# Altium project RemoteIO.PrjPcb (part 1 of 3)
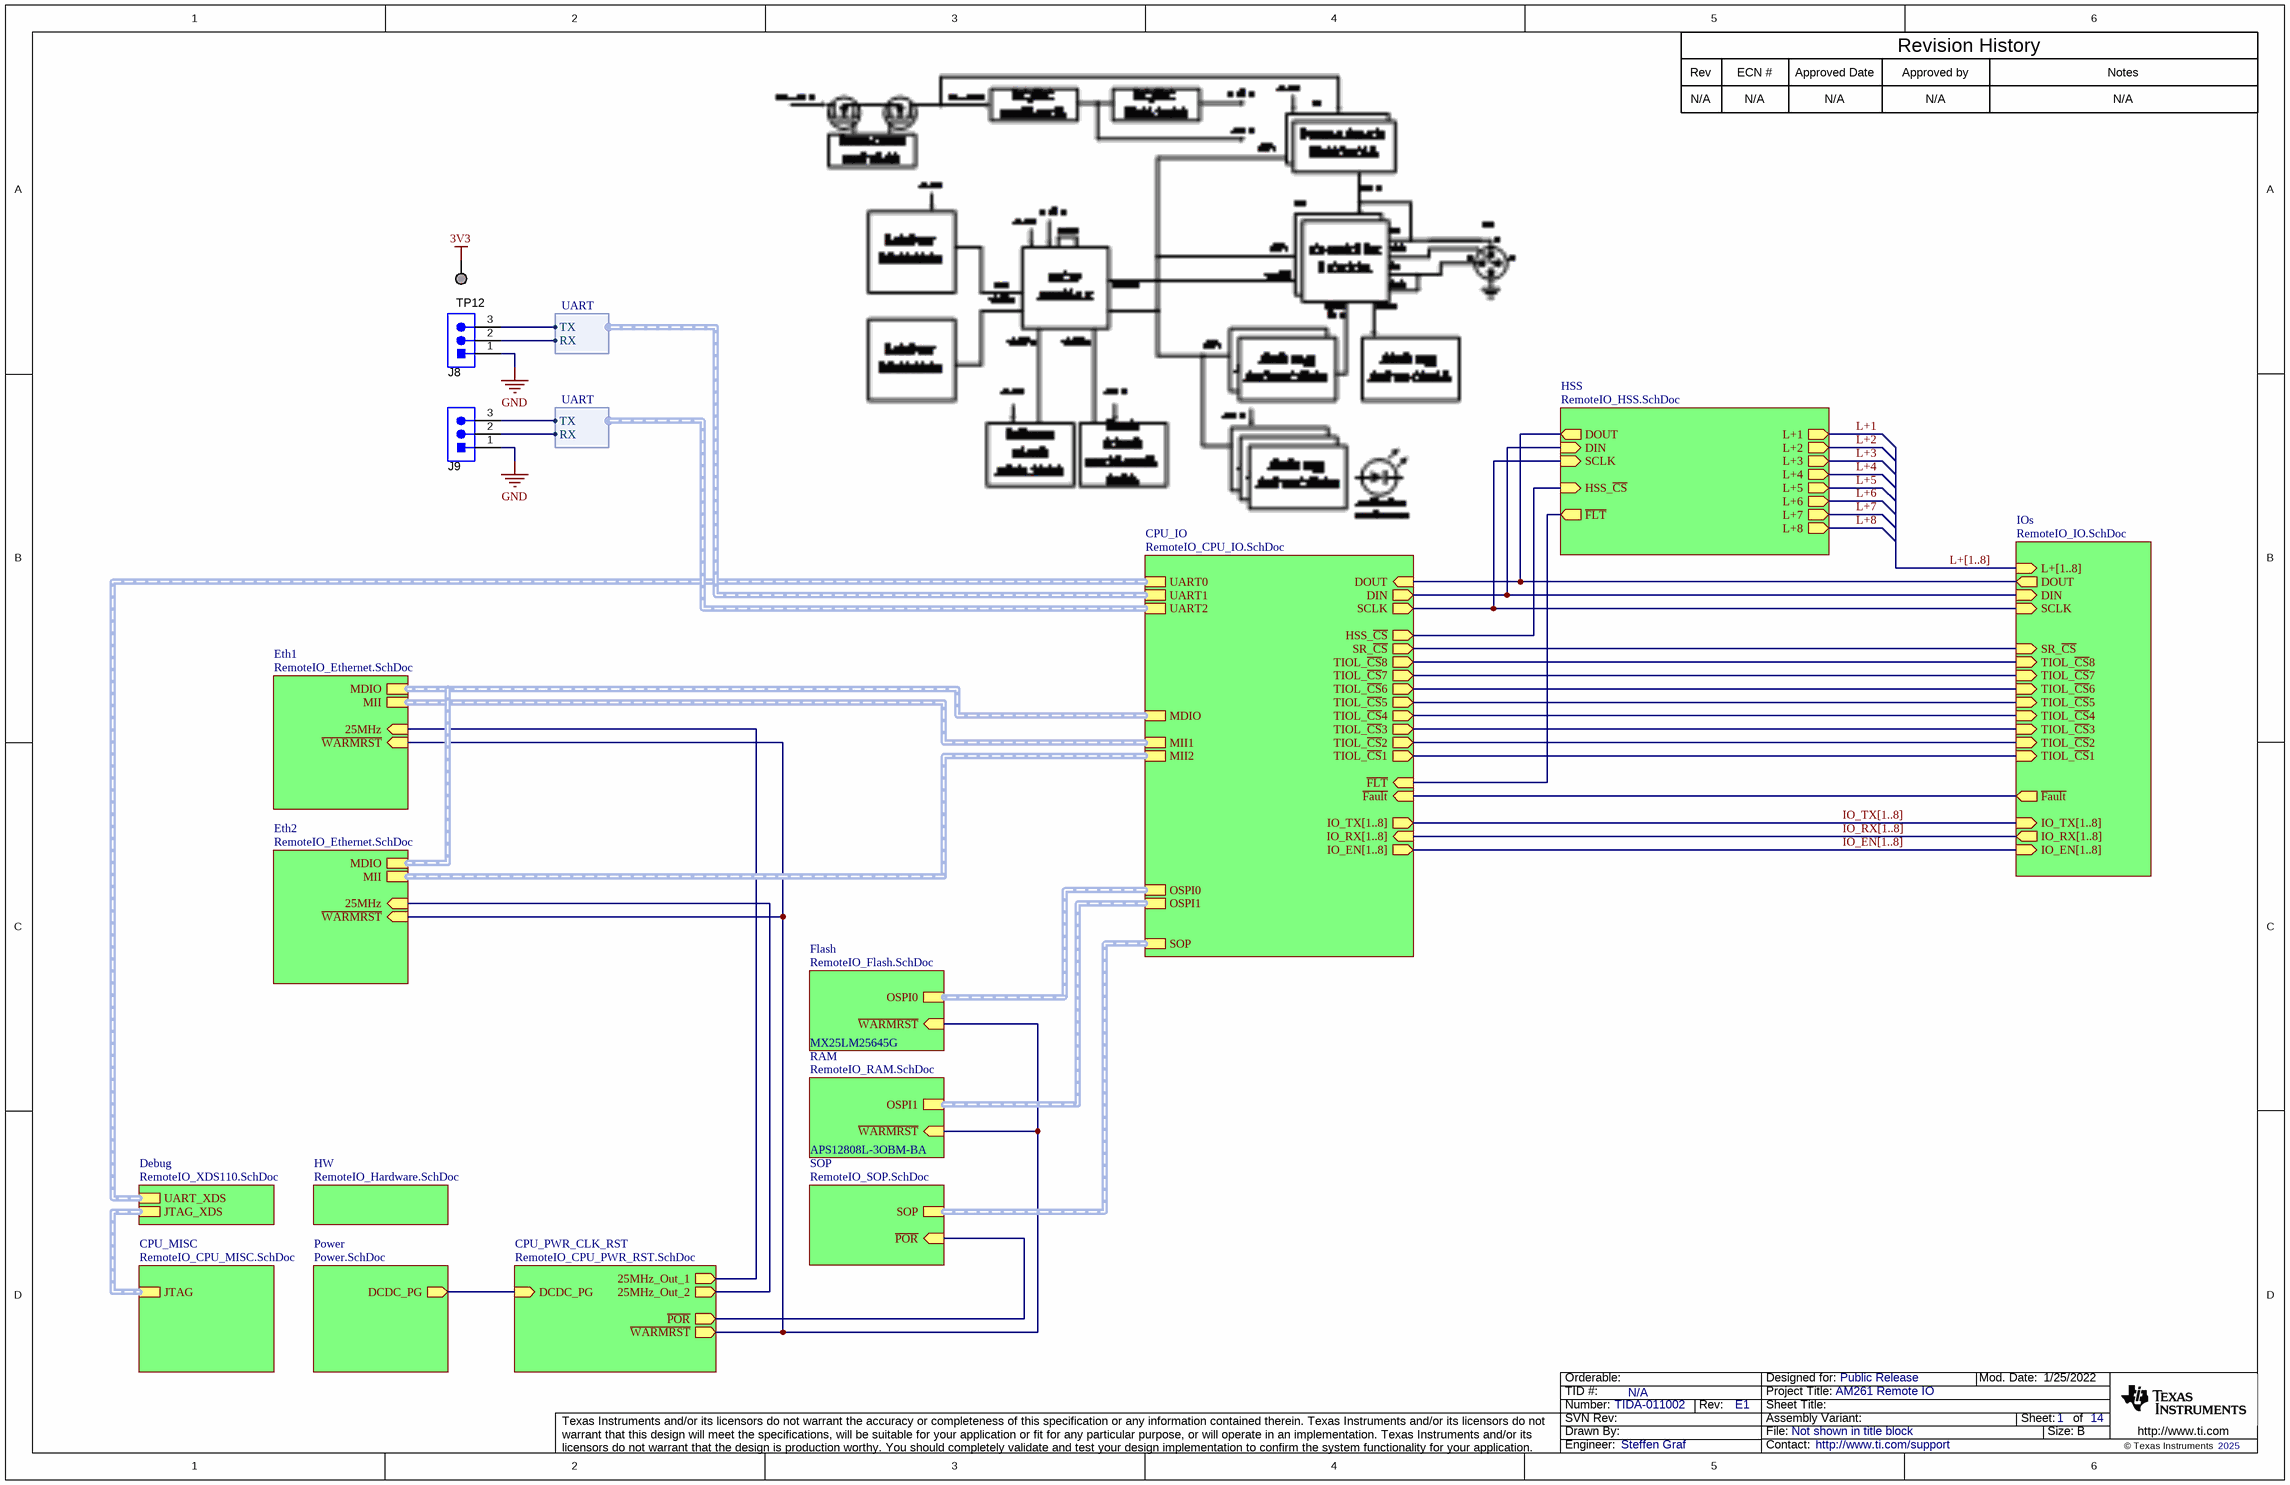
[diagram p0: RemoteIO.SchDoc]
CopyrightYear: 2025; PCB_Layout: Steffen Graf; PCB_Rev: E1; PRJ_Customer: Public Release; PRJ_Engineer: Steffen Graf; PRJ_Number: TIDA-011002; PRJ_Title: AM261 Remote IO; SCH_Rev: E1; TechSupport: http://www.ti.com/support; TID: N/A
13 sheets, 600 parts. Net scope: hierarchical (ports join the sheet entries above them; power ports are global).
Board file: RemoteIO.PcbDoc
Sheets:
  RemoteIO.SchDoc
    Eth1 = RemoteIO_Ethernet.SchDoc
    Eth2 = RemoteIO_Ethernet.SchDoc
    CPU_IO = RemoteIO_CPU_IO.SchDoc
    IOs = RemoteIO_IO.SchDoc
      IO1 = RemoteIO_IOLinkPort.SchDoc
      IO2 = RemoteIO_IOLinkPort.SchDoc
      IO3 = RemoteIO_IOLinkPort.SchDoc
      IO4 = RemoteIO_IOLinkPort.SchDoc
      IO5 = RemoteIO_IOLinkPort.SchDoc
      IO6 = RemoteIO_IOLinkPort.SchDoc
      IO7 = RemoteIO_IOLinkPort.SchDoc
      IO8 = RemoteIO_IOLinkPort.SchDoc
    HW = RemoteIO_Hardware.SchDoc
    HSS = RemoteIO_HSS.SchDoc
    Flash = RemoteIO_Flash.SchDoc
    RAM = RemoteIO_RAM.SchDoc
    SOP = RemoteIO_SOP.SchDoc
    CPU_PWR_CLK_RST = RemoteIO_CPU_PWR_RST.SchDoc
    CPU_MISC = RemoteIO_CPU_MISC.SchDoc
    Debug = RemoteIO_XDS110.SchDoc

## Sheet RemoteIO.SchDoc
size 431 x 279 mm; Date: Not shown in title block; ApprovedBy: Not shown in title block; CheckedBy: Not shown in title block; Author: Not shown in title block; CompanyName: Not shown in title block; Engineer: Not shown in title block; Organization: Not shown in title block; Address1: Not shown in title block; Address2: Not shown in title block; Address3: Not shown in title block; Address4: Not shown in title block; DocumentNumber: 1; Revision: Use project parameter SCH_Rev; SheetNumber: 1; SheetTotal: 14; PageSetup: Record=PageOptions¦CenterHorizontal=True¦CenterVertical=True¦PrintScale=1.00¦XCorrection=1.00¦YCorrection=1.00¦PrintKind=0¦BorderSize=5000000¦LeftOffset=0¦BottomOffset=0¦Orientation=2¦PaperLength=1000¦PaperWidth=1000¦Scale=100¦PaperSource=15¦PrintQuality=600¦MediaType=1¦DitherType=10¦PaperKind=Letter¦PrintScaleMode=1

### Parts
J8  61300311121  [WURTH_61300311121]  (value not drawn)
J9  61300311121  [WURTH_61300311121]  (value not drawn)
TP12  TESTPOINT  [TP_50MIL-25MILHOLE]  (value not drawn)  (no BOM)

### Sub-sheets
CPU_IO = RemoteIO_CPU_IO.SchDoc: DOUT (in), DIN (out), SCLK (out), HSS_~{CS} (out), SR_~{CS} (out), TIOL_~{CS}8 (out), TIOL_~{CS}7 (out), TIOL_~{CS}6 (out), TIOL_~{CS}5 (out), TIOL_~{CS}4 (out), TIOL_~{CS}3 (out), TIOL_~{CS}2 (out), TIOL_~{CS}1 (out), ~{FLT} (in), ~{Fault} (in), IO_TX[1..8] (out), IO_RX[1..8] (in), IO_EN[1..8] (out), MII1 (harness MII), MII2 (harness MII), MDIO (harness MDIO), UART0 (harness UART), UART1 (harness UART), OSPI0 (harness OSPI), OSPI1 (harness OSPI), SOP (harness SOP), UART2 (harness UART)
CPU_MISC = RemoteIO_CPU_MISC.SchDoc: JTAG (harness JTAG)
CPU_PWR_CLK_RST = RemoteIO_CPU_PWR_RST.SchDoc: DCDC_PG (in), ~{POR} (out), ~{WARMRST} (out), 25MHz_Out_1 (out), 25MHz_Out_2 (out)
Debug = RemoteIO_XDS110.SchDoc: JTAG_XDS (harness JTAG), UART_XDS (harness UART)
Eth1 = RemoteIO_Ethernet.SchDoc: MII, MDIO, 25MHz (in), ~{WARMRST} (in)
Eth2 = RemoteIO_Ethernet.SchDoc: MII, MDIO, 25MHz (in), ~{WARMRST} (in)
Flash = RemoteIO_Flash.SchDoc: OSPI0 (harness OSPI), ~{WARMRST} (in)
HSS = RemoteIO_HSS.SchDoc: L+1 (out), L+2 (out), L+3 (out), L+4 (out), L+5 (out), L+6 (out), L+7 (out), L+8 (out), HSS_~{CS} (in), SCLK (in), DIN (in), DOUT (out), ~{FLT} (out)
HW = RemoteIO_Hardware.SchDoc: no entries
IOs = RemoteIO_IO.SchDoc: SR_~{CS} (in), ~{Fault} (out), TIOL_~{CS}8 (in), TIOL_~{CS}7 (in), TIOL_~{CS}6 (in), TIOL_~{CS}5 (in), TIOL_~{CS}4 (in), TIOL_~{CS}3 (in), TIOL_~{CS}2 (in), TIOL_~{CS}1 (in), SCLK (in), DIN (in), DOUT (out), L+[1..8] (in), IO_RX[1..8] (out), IO_TX[1..8] (in), IO_EN[1..8] (in)
Power = Power.SchDoc (file not in this document): DCDC_PG (out)
RAM = RemoteIO_RAM.SchDoc: OSPI1, ~{WARMRST} (in)
SOP = RemoteIO_SOP.SchDoc: SOP (harness SOP), ~{POR} (in)

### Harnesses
UART: TX, RX

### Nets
3V3: TP12.1
GND: J8.1 J9.1
25MHz: sheet Eth1/25MHz, sheet CPU_PWR_CLK_RST/25MHz_Out_1
25MHz: sheet Eth2/25MHz, sheet CPU_PWR_CLK_RST/25MHz_Out_2  [a separate net that carries the same name]
~{Fault}: sheet CPU_IO/~{Fault}, sheet IOs/~{Fault}
~{FLT}: sheet CPU_IO/~{FLT}, sheet HSS/~{FLT}
~{POR}: sheet SOP/~{POR}, sheet CPU_PWR_CLK_RST/~{POR}
~{WARMRST}: sheet Eth1/~{WARMRST}, sheet Eth2/~{WARMRST}, sheet Flash/~{WARMRST}, sheet RAM/~{WARMRST}, sheet CPU_PWR_CLK_RST/~{WARMRST}
CS1: sheet CPU_IO/TIOL_~{CS}1, sheet IOs/TIOL_~{CS}1
CS2: sheet CPU_IO/TIOL_~{CS}2, sheet IOs/TIOL_~{CS}2
CS3: sheet CPU_IO/TIOL_~{CS}3, sheet IOs/TIOL_~{CS}3
CS4: sheet CPU_IO/TIOL_~{CS}4, sheet IOs/TIOL_~{CS}4
CS5: sheet CPU_IO/TIOL_~{CS}5, sheet IOs/TIOL_~{CS}5
CS6: sheet CPU_IO/TIOL_~{CS}6, sheet IOs/TIOL_~{CS}6
CS7: sheet CPU_IO/TIOL_~{CS}7, sheet IOs/TIOL_~{CS}7
CS8: sheet CPU_IO/TIOL_~{CS}8, sheet IOs/TIOL_~{CS}8
DCDC_PG: sheet Power/DCDC_PG, sheet CPU_PWR_CLK_RST/DCDC_PG
DIN: sheet CPU_IO/DIN, sheet IOs/DIN, sheet HSS/DIN
DOUT: sheet CPU_IO/DOUT, sheet IOs/DOUT, sheet HSS/DOUT
HSS_~{CS}: sheet CPU_IO/HSS_~{CS}, sheet HSS/HSS_~{CS}
SCLK: sheet CPU_IO/SCLK, sheet IOs/SCLK, sheet HSS/SCLK
SR_~{CS}: sheet CPU_IO/SR_~{CS}, sheet IOs/SR_~{CS}
UART1_RX: J8.2 ; sheet CPU_IO/UART1.RX
UART1_TX: J8.3 ; sheet CPU_IO/UART1.TX
NetJ9_2: J9.2 ; sheet CPU_IO/UART2.RX
NetJ9_3: J9.3 ; sheet CPU_IO/UART2.TX

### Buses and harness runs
bus IO_EN[1..8] = sheet CPU_IO/IO_EN[1..8] = sheet IOs/IO_EN[1..8]
bus IO_RX[1..8] = sheet CPU_IO/IO_RX[1..8] = sheet IOs/IO_RX[1..8]
bus IO_TX[1..8] = sheet CPU_IO/IO_TX[1..8] = sheet IOs/IO_TX[1..8]
bus L+[1..8] = sheet IOs/L+[1..8]
harness sheet CPU_IO/MDIO = sheet Eth1/MDIO = sheet Eth2/MDIO
harness sheet CPU_IO/MII1 = sheet Eth1/MII
harness sheet CPU_IO/MII2 = sheet Eth2/MII
harness sheet CPU_IO/OSPI0 = sheet Flash/OSPI0
harness sheet CPU_IO/OSPI1 = sheet RAM/OSPI1
harness sheet CPU_IO/SOP = sheet SOP/SOP
harness sheet CPU_IO/UART0 = sheet Debug/UART_XDS
harness sheet CPU_MISC/JTAG = sheet Debug/JTAG_XDS

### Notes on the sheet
- Rev
- N/A
- ECN #
- Approved Date
- Approved by
- Revision History
- Notes
- MX25LM25645G
- APS12808L-3OBM-BA

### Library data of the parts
J8 J9 = CMP-0054796-4: Header, 2.54 mm, 3x1, Gold, TH; Manufacturer: Wurth Elektronik; Green_REACh: Passed; CT: FALSE; CNHeader: TRUE; Green_Lifecycle: Active
TP12 = CMP-0078143-4: TEST POINT.  No entry in BOM.

## Sheet RemoteIO_Ethernet.SchDoc
size 431 x 279 mm; Date: Not shown in title block; ApprovedBy: Not shown in title block; CheckedBy: Not shown in title block; Author: Not shown in title block; CompanyName: Not shown in title block; Engineer: Not shown in title block; Organization: Not shown in title block; Address1: Not shown in title block; Address2: Not shown in title block; Address3: Not shown in title block; Address4: Not shown in title block; DocumentNumber: 11; Revision: Use project parameter SCH_Rev; SheetNumber: 11; SheetTotal: 14; PageSetup: Record=PageOptions¦CenterHorizontal=True¦CenterVertical=True¦PrintScale=1.00¦XCorrection=1.00¦YCorrection=1.00¦PrintKind=0¦BorderSize=5000000¦LeftOffset=0¦BottomOffset=0¦Orientation=2¦PaperLength=1000¦PaperWidth=1000¦Scale=100¦PaperSource=15¦PrintQuality=600¦MediaType=1¦DitherType=10¦PaperKind=Letter¦PrintScaleMode=1
Used 2 times, as channels Eth1, Eth2. Parts and nets are listed once, with the designators drawn on the sheet.
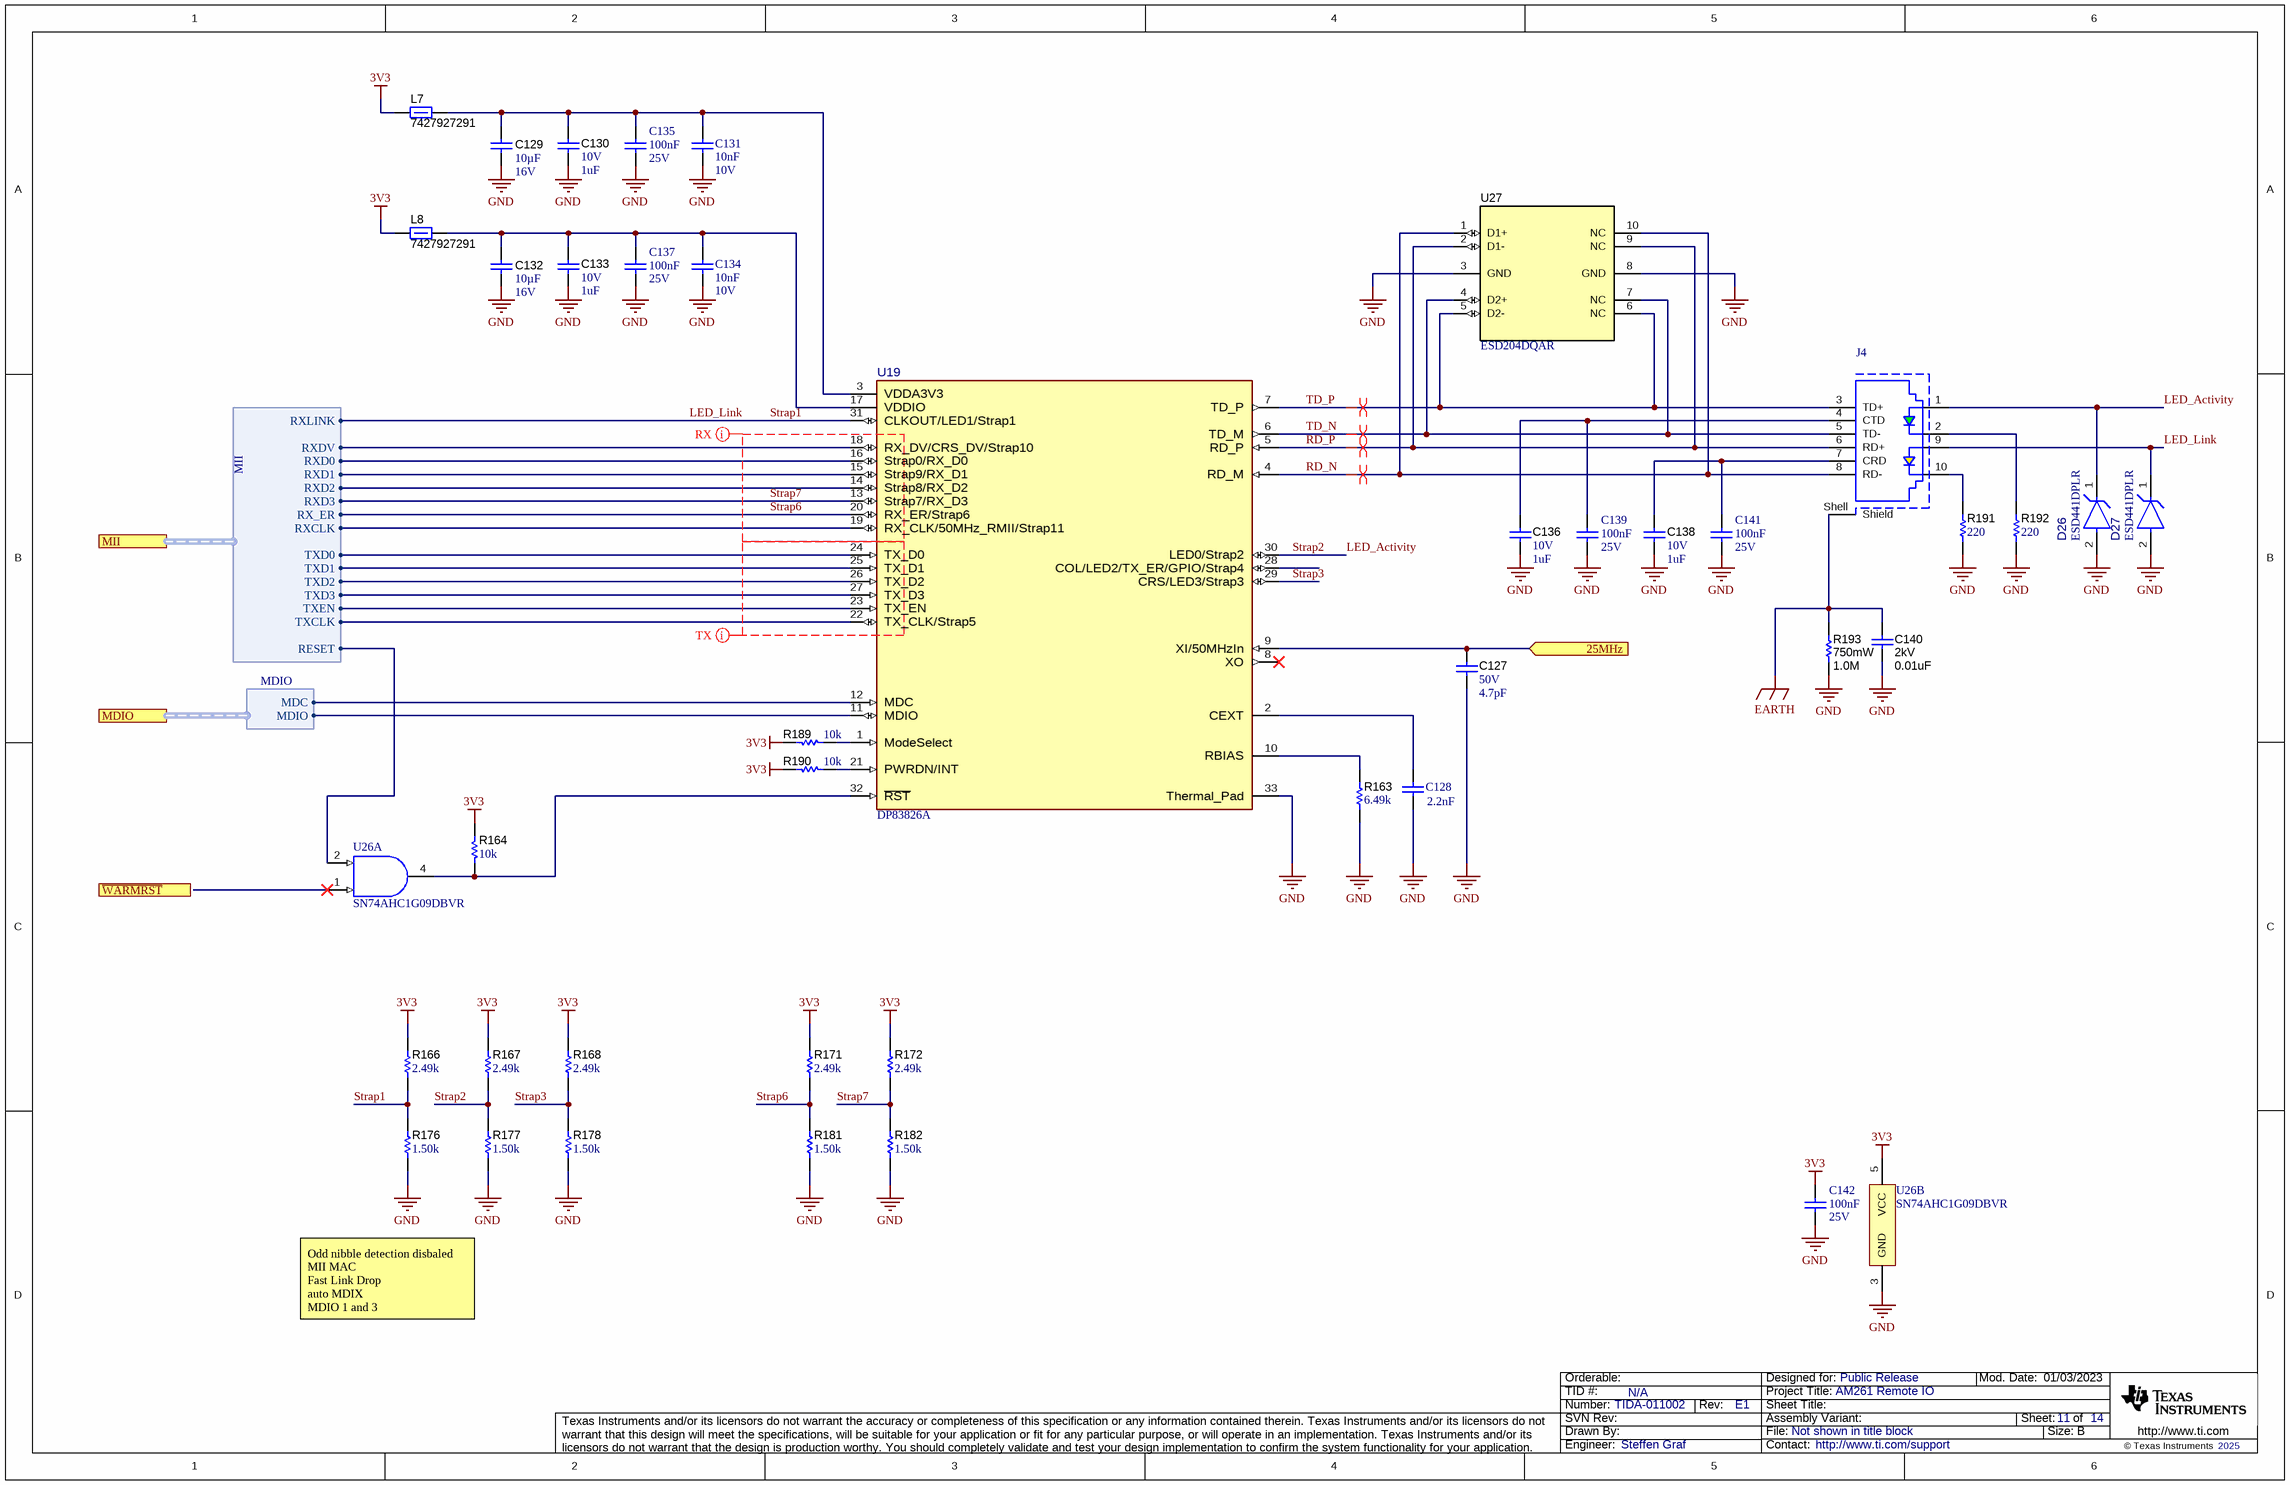
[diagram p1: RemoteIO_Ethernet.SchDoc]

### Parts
C127  VDC_V: 50V  ValueDisplayed: 4.7pF  [0402]  (hidden comment: GRM1555C1H4R7WA01D)
C128  Cap_F: 2.2nF  [WCAP-CSGP_0402_L1W0.5H0.5]  (hidden comment: 885012205063)
C129  ValueDisplayed: 10µF  VDC_V: 16V  [1206]  (hidden comment: 885012208041)
C130  VDC_V: 10V  ValueDisplayed: 1uF  [0402]  (hidden comment: 885012105012)
C131  Cap_F: 10nF  Rated Voltage (DC): 10V  [WCAP-CSGP_0402_L1W0.5H0.5]  (hidden comment: 885012205012)
C132  ValueDisplayed: 10µF  VDC_V: 16V  [1206]  (hidden comment: 885012208041)
C133  VDC_V: 10V  ValueDisplayed: 1uF  [0402]  (hidden comment: 885012105012)
C134  Cap_F: 10nF  Rated Voltage (DC): 10V  [WCAP-CSGP_0402_L1W0.5H0.5]  (hidden comment: 885012205012)
C135  Cap_F: 100nF  Rated Voltage (DC): 25V  [WCAP-CSGP_0402_L1W0.5H0.5]  (hidden comment: 885012105018)
C136  VDC_V: 10V  ValueDisplayed: 1uF  [0402]  (hidden comment: 885012105012)
C137  Cap_F: 100nF  Rated Voltage (DC): 25V  [WCAP-CSGP_0402_L1W0.5H0.5]  (hidden comment: 885012105018)
C138  VDC_V: 10V  ValueDisplayed: 1uF  [0402]  (hidden comment: 885012105012)
C139  Cap_F: 100nF  Rated Voltage (DC): 25V  [WCAP-CSGP_0402_L1W0.5H0.5]  (hidden comment: 885012105018)
C140  VDC_V: 2kV  ValueDisplayed: 0.01uF  [1825]  (hidden comment: 1825GC103KAT1A)
C141  Cap_F: 100nF  Rated Voltage (DC): 25V  [WCAP-CSGP_0402_L1W0.5H0.5]  (hidden comment: 885012105018)
C142  Cap_F: 100nF  Rated Voltage (DC): 25V  [WCAP-CSGP_0402_L1W0.5H0.5]  (hidden comment: 885012105018)
D26  ESD441DPLR  [DPL0002A-MFG]
D27  ESD441DPLR  [DPL0002A-MFG]
J4  7498011211  [7498011211]  (value not drawn)
L7  7427927291  [0402]
L8  7427927291  [0402]
R163  ValueDisplayed: 6.49k  [0402]  (hidden comment: CRCW04026K49FKED)
R164  ValueDisplayed: 10k  [0402]  (hidden comment: CRCW040210K0JNED)
R166  ValueDisplayed: 2.49k  [0402]  (hidden comment: CRCW04022K49FKED)
R167  ValueDisplayed: 2.49k  [0402]  (hidden comment: CRCW04022K49FKED)
R168  ValueDisplayed: 2.49k  [0402]  (hidden comment: CRCW04022K49FKED)
R171  ValueDisplayed: 2.49k  [0402]  (hidden comment: CRCW04022K49FKED)
R172  ValueDisplayed: 2.49k  [0402]  (hidden comment: CRCW04022K49FKED)
R176  ValueDisplayed: 1.50k  [0402]  (hidden comment: CRCW04021K50FKED)
R177  ValueDisplayed: 1.50k  [0402]  (hidden comment: CRCW04021K50FKED)
R178  ValueDisplayed: 1.50k  [0402]  (hidden comment: CRCW04021K50FKED)
R181  ValueDisplayed: 1.50k  [0402]  (hidden comment: CRCW04021K50FKED)
R182  ValueDisplayed: 1.50k  [0402]  (hidden comment: CRCW04021K50FKED)
R189  ValueDisplayed: 10k  [0402]  (hidden comment: CRCW040210K0JNED)
R190  ValueDisplayed: 10k  [0402]  (hidden comment: CRCW040210K0JNED)
R191  ValueDisplayed: 220  [0603]  (hidden comment: CRCW0603220RJNEA)
R192  ValueDisplayed: 220  [0603]  (hidden comment: CRCW0603220RJNEA)
R193  Power_W: 750mW  ValueDisplayed: 1.0M  [2010]  (hidden comment: CRCW20101M00JNEF)
U19  DP83826A  [RHB0032M-MFG]
U26  SN74AHC1G09DBVR  [DBV0005A_N]  (parts A,B of 2)
U27  ESD204DQAR  [DQA0010A]

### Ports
25MHz (in), MDIO (harness MDIO), MII (harness MII), ~{WARMRST} (in)

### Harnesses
MII: RXDV, RXD0, RXD1, RXD2, RXD3, RX_ER, RXCLK, RXLINK, TXD0, TXD1, TXD2, TXD3, TXEN, TXCLK, RESET
MDIO: MDC, MDIO

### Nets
3V3: C142.2 L7.2 L8.2 R164.2 R166.2 R167.2 R168.2 R171.2 R172.2 R189.2 R190.2 U26.5(VCC)
EARTH: C140.2 J4.Shell(Shield) R193.1
GND: C127.2 C128.1 C129.2 C130.2 C131.1 C132.2 C133.2 C134.1 C135.1 C136.2 C137.1 C138.2 C139.1 C140.1 C141.1 C142.1 D26.2(GND) D27.2(GND) R163.1 R176.1 R177.1 R178.1 R181.1 R182.1 R191.1 R192.1 R193.2 U19.33(Thermal_Pad) U26.3(GND) U27.3(GND) U27.8(GND)
25MHz: C127.1 U19.9(XI/50MHzIn) ; port 25MHz
LED_Activity: D26.1(IO) J4.1 R167.1 R177.2 U19.30(LED0/Strap2)  [also labelled Strap2]
LED_Link: D27.1(IO) J4.9 R166.1 R176.2 U19.31(CLKOUT/LED1/Strap1) ; port MII.RXLINK  [also labelled Strap1]
RD_N: J4.8(RD-) U19.4(RD_M) U27.1(D1+) U27.10(NC)
RD_P: J4.6(RD+) U19.5(RD_P) U27.2(D1-) U27.9(NC)
Strap3: R168.1 R178.2 U19.29(CRS/LED3/Strap3)
Strap6: R171.1 R181.2 U19.20(RX_ER/Strap6) ; port MII.RX_ER
Strap7: R172.1 R182.2 U19.13(Strap7/RX_D3) ; port MII.RXD3
TD_N: J4.5(TD-) U19.6(TD_M) U27.4(D2+) U27.7(NC)
TD_P: J4.3(TD+) U19.7(TD_P) U27.5(D2-) U27.6(NC)
NetC128_2: C128.2 U19.2(CEXT)
NetC129_1: C129.1 C130.1 C131.2 C135.2 L7.1 U19.3(VDDA3V3)
NetC132_1: C132.1 C133.1 C134.2 C137.2 L8.1 U19.17(VDDIO)
NetC136_1: C136.1 C139.2 J4.4(CTD)
NetC138_1: C138.1 C141.2 J4.7(CRD)
NetJ4_2: J4.2 R192.2
NetJ4_10: J4.10 R191.2
NetR163_2: R163.2 U19.10(RBIAS)
NetR164_1: R164.1 U19.32(~{RST}) U26.4(Y)
NetR189_1: R189.1 U19.1(ModeSelect)
NetR190_1: R190.1 U19.21(PWRDN/INT)
NetU19_11: U19.11(MDIO) ; port MDIO.MDIO
NetU19_12: U19.12(MDC) ; port MDIO.MDC
NetU19_14: U19.14(Strap8/RX_D2) ; port MII.RXD2
NetU19_15: U19.15(Strap9/RX_D1) ; port MII.RXD1
NetU19_16: U19.16(Strap0/RX_D0) ; port MII.RXD0
NetU19_18: U19.18(RX_DV/CRS_DV/Strap10) ; port MII.RXDV
NetU19_19: U19.19(RX_CLK/50MHz_RMII/Strap11) ; port MII.RXCLK
NetU19_22: U19.22(TX_CLK/Strap5) ; port MII.TXCLK
NetU19_23: U19.23(TX_EN) ; port MII.TXEN
NetU19_24: U19.24(TX_D0) ; port MII.TXD0
NetU19_25: U19.25(TX_D1) ; port MII.TXD1
NetU19_26: U19.26(TX_D2) ; port MII.TXD2
NetU19_27: U19.27(TX_D3) ; port MII.TXD3
NetU26_2: U26.2(B) ; port MII.RESET

Not connected (* = marked no-connect by the designer): U19 8(XO)* 28(COL/LED2/TX_ER/GPIO/Strap4); U26 1(A)*

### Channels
Eth1: designators end in .1; ports 25MHz=25MHz ~{WARMRST}=~{WARMRST}
Eth2: designators end in .2; ports 25MHz=25MHz ~{WARMRST}=~{WARMRST}

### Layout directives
differential pair; differential pair class D100: RD_N_Eth1, RD_P_Eth1, TD_N_Eth1, TD_P_Eth1
net class MII_TX: (no net found under the mark)
net class MII_RX: Strap6, Strap7

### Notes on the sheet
- Odd nibble detection disbaled
  MII MAC
  Fast Link Drop
  auto MDIX
  MDIO 1 and 3

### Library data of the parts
C127 = CMP-0006473-2: CAP, CERM, 4.7 pF, 50 V, +/- 1%, C0G/NP0, 0402; Manufacturer: MuRata; TaMin_C: -55°C; Polarized: N; SizeAreaWB_mm2: 3; Value1: Unknown; U/M: EA; Value: 4.7pF; TaMax_C: 125°C; SizeZ_mm: 0.6; SizeX_mm: 1; SizeY_mm: 0.5; AEC Category: Q200
C128 = CMP-0119293-1: WCAP-CSGP Multilayer Ceramic Chip Capacitor, General Purpose, size 0402, X7R, 2.2nF, 50VDC; Manufacturer: Wurth Elektronik; Capacitance Tolerance: +/-10%; Case/Size Code: 0402; Dissipation Factor: 2.5%; Insulation Resistance: 10GOhm; Rated Voltage (DC): 50V; Technical Reference: X7R0402222K050DFCT10000
C129 C132 = CMP-0750070-1: CAP, CERM, 10 µF, 16 V,+/- 10%, X7R, 1206; Manufacturer: Wurth Elektronik; SizeArea_mm2: 5.12; SizeZ_mm: 1.35; Polarized: N; SizeAreaWB_mm2: 10.92; AEC Category: Q200; SizeX_mm: 3.2; TaMin_C: -55°C; U/M: EA; TaMax_C: 125°C; Value: 10uF; SizeY_mm: 1.6
C130 C133 C136 C138 = CMP-0064924-2: CAP, CERM, 1 uF, 10 V,+/- 20%, X5R, 0402; Manufacturer: Wurth Elektronik; TaMin_C: -55°C; Polarized: N; SizeAreaWB_mm2: 3; Value1: Unknown; U/M: EA; Value: 1uF; TaMax_C: 85°C; SizeZ_mm: 0.6; SizeX_mm: 1; SizeY_mm: 0.5; Cap_F: 1µF; AEC Category: Q200
C131 C134 = CMP-0119242-1: WCAP-CSGP Multilayer Ceramic Chip Capacitor, General Purpose, size 0402, X7R, 10nF, 10VDC; Manufacturer: Wurth Elektronik; Capacitance Tolerance: +/-10%; Case/Size Code: 0402; Dissipation Factor: 5%; Insulation Resistance: 10GOhm; Technical Reference: X7R0402103K010DFCT10000
C135 C137 C139 C141 C142 = CMP-0119143-1: WCAP-CSGP Multilayer Ceramic Chip Capacitor, General Purpose, size 0402, X5R, 100nF, 25VDC; Manufacturer: Wurth Elektronik; PartNumber: '885012105018; Capacitance Tolerance: +/-20%; Case/Size Code: 0402; Dissipation Factor: 10%; Insulation Resistance: 5GOhm; Technical Reference: X5R0402104M025DFCT10000
C140 = CMP-0009301-2: CAP, CERM, 0.01 uF, 2000 V, +/- 10%, X7R, 1825; Manufacturer: AVX; TaMin_C: -55°C; Polarized: N; SizeAreaWB_mm2: 54.6; Value1: Unknown; U/M: EA; Value: 0.01uF; TaMax_C: 125°C; SizeZ_mm: 1.1; SizeX_mm: 4.5; SizeY_mm: 6.4; Value2: 2000V; SizeArea_mm2: 28.8; Cap_F: 10nF; AEC Category: Q200
D26 D27 = CMP-0120655-1: 1-pF, 5.5-V, 30-KV ESD protection device in 0201 package 2-X2SON -40 to 125; Manufacturer: Texas Instruments; SizeZ_mm: 0.32mm; AEC Qualified: No; Breakdown Voltage: 6V; Cap_F: 1pF; Clamping Voltage: 3.8V; Direction: Unidirectional; Ipp: 6A; Number Of Channels: 1; Ppk: 45W; Standoff Height: 0mm; TaMax_C: +150°C; TaMin_C: -55°C; VRWM: 5.5V
J4 = 7498011211: WE-RJ45 LAN Transformer, SMT, 10/100 Base-T, Tab Down, 1 Port; Manufacturer: Wurth Elektronik; LED: green-yellow; Number of Ports: 1; PoE: non-PoE; Shield Tabs: Yes; USB: No USB
L7 L8 = CMP-0003233-1: Ferrite Bead, 600 ohm @ 100 MHz, 0.3 A, 0402; Manufacturer: Wurth Elektronik; Ztyp@1GHz_Ohm: 385.838; ZTyp@100MHz_Ohm: 600; SizeAreaWB_mm2: 3; DCR_ohm: 0.6; Value1: 0.6 ohm; Value: 600 ohm; Imax_A: 300mA; SizeX_mm: 1; SizeY_mm: 0.5; Value2: 0.3A
R163 = CMP-0026515-2: RES, 6.49 k, 1%, 0.063 W, AEC-Q200 Grade 0, 0402; Manufacturer: Vishay-Dale; Power_W: 63mW; TempCo: 100 ppm/C; Value_Code: 6k49; Value: 6.49k; EIA_Code: E96; SizeX_mm: 1; SizeY_mm: 0.5; SizeZ_mm: 0.6; Value2: 0.063W; AEC Qualified: Y; VDC_V: 50V; AEC Category: Q200; AEC Grade: 0
R164 R189 R190 = CMP-0026825-5: RES, 10 k, 5%, 0.063 W, AEC-Q200 Grade 0, 0402; Manufacturer: Vishay-Dale; Power_W: 63mW; TempCo: 200 ppm/C; Value_Code: 10k0; Value: 10k; EIA_Code: E24; SizeX_mm: 1; SizeY_mm: 0.5; SizeZ_mm: 0.6; Value2: 0.063W; AEC Qualified: Y; VDC_V: 50V; AEC Category: Q200; AEC Grade: 0
R166-R168 R171 R172 = CMP-0026237-2: RES, 2.49 k, 1%, 0.063 W, AEC-Q200 Grade 0, 0402; Manufacturer: Vishay-Dale; Power_W: 63mW; TempCo: 100 ppm/C; Value_Code: 2k49; Value: 2.49k; EIA_Code: E96; SizeX_mm: 1; SizeY_mm: 0.5; SizeZ_mm: 0.6; Value2: 0.063W; AEC Qualified: Y; VDC_V: 50V; AEC Category: Q200; AEC Grade: 0
R176-R178 R181 R182 = CMP-0026088-3: RES, 1.50 k, 1%, 0.063 W, AEC-Q200 Grade 0, 0402; Manufacturer: Vishay-Dale; Power_W: 63mW; TempCo: 100 ppm/C; Value_Code: 1k50; Value: 1.50k; EIA_Code: E96; Res_ohm: 1.5k; SizeX_mm: 1; SizeY_mm: 0.5; SizeZ_mm: 0.6; Value2: 0.063W; AEC Qualified: Y; VDC_V: 50V; AEC Category: Q200; AEC Grade: 0
R191 R192 = CMP-0025756-4: RES, 220, 5%, 0.1 W, AEC-Q200 Grade 0, 0603; Manufacturer: Vishay-Dale; Power_W: 100mW; TempCo: 200 ppm/C; Value_Code: 220R; Value: 220; EIA_Code: E24; SizeX_mm: 1.6; SizeY_mm: 0.8; SizeZ_mm: 1; Value2: 0.1W; SizeArea_mm2: 1.28; AEC Qualified: Y; VDC_V: 75V; AEC Category: Q200; AEC Grade: 0
R193 = CMP-0016081-3: RES, 1.0 M, 5%, 0.75 W, AEC-Q200 Grade 0, 2010; Manufacturer: Vishay-Dale; TempCo: 200 ppm/C; Value_Code: 1M00; Value: 1.0Meg; EIA_Code: E24; Res_ohm: 1M; SizeX_mm: 5; SizeY_mm: 2.5; SizeZ_mm: 1.66; Value2: 0.75W; SizeArea_mm2: 12.5; AEC Qualified: Y; VDC_V: 400V; AEC Grade: 0; AEC Category: Q200
U19 = CMP-0124715-2: Deterministic, Low-Latency, Low-Power, 10/100 Mbps, Industrial Ethernet PHY; Manufacturer: Texas Instruments; SizeZ_mm: 1mm; AEC Qualified: No; Data Rate: 100Mbits/s; Interface: Ethernet,Other; Max Supply Voltage: 3.6V; Min Supply Voltage: 1.62V; Number Of Channels: 1; Simplex Duplex: Full-Duplex; Standoff Height: 0mm; TaMax_C: +85°C; TaMin_C: -40°C; AEC Category: Q200; CompType: IC
U26 = CMP-0051264-2: Single 2-Input Positive–AND Gate with Open Drain Output,  DBV0005A (SOT-23-5); Manufacturer: Texas Instruments; 3-State Output: No; Input Type: CMOS; Bits(#): 1; F @ Nom Voltage(Max)(Mhz): 75; tpd @ Nom Voltage(Max)(ns): 11,7.5; Voltage(Nom)(V): 3.3,5; Output Drive (IOL/IOH)(Max)(mA): 50/-50; Gate Type: AND; VCC(Max)(V): 5.5; ICC @ Nom Voltage(Max)(mA): 0.01; VCC(Min)(V): 2; Logic: True; Rating: Catalog; AEC Category: Q200; AEC Qualified: N; CompType: IC; SizeAreaWB_mm2: 14.82; SizeArea_mm2: 8.12; SizeX_mm: 2.8; SizeY_mm: 2.9; SizeZ_mm: 1.45
U27 = CMP-0079927-2: ESD204, DQA0010A (USON-10); Alternate PartNumber: ESD204DQAT; Alternate Manufacturer: Texas Instruments; SizeAreaWB_mm2: 7; SizeZ_mm: 0.55; SizeX_mm: 1; SizeY_mm: 2.5; CompType: IC; AEC Qualified: N; AEC Category: Q200

## Sheet RemoteIO_CPU_IO.SchDoc
size 431 x 279 mm; Date: Not shown in title block; ApprovedBy: Not shown in title block; CheckedBy: Not shown in title block; Author: Not shown in title block; CompanyName: Not shown in title block; Engineer: Not shown in title block; Organization: Not shown in title block; Address1: Not shown in title block; Address2: Not shown in title block; Address3: Not shown in title block; Address4: Not shown in title block; DocumentNumber: 5; Revision: Use project parameter SCH_Rev; SheetNumber: 5; SheetTotal: 14; PageSetup: Record=PageOptions¦CenterHorizontal=True¦CenterVertical=True¦PrintScale=1.00¦XCorrection=1.00¦YCorrection=1.00¦PrintKind=0¦BorderSize=5000000¦LeftOffset=0¦BottomOffset=0¦Orientation=2¦PaperLength=1000¦PaperWidth=1000¦Scale=100¦PaperSource=15¦PrintQuality=600¦MediaType=1¦DitherType=10¦PaperKind=Letter¦PrintScaleMode=1
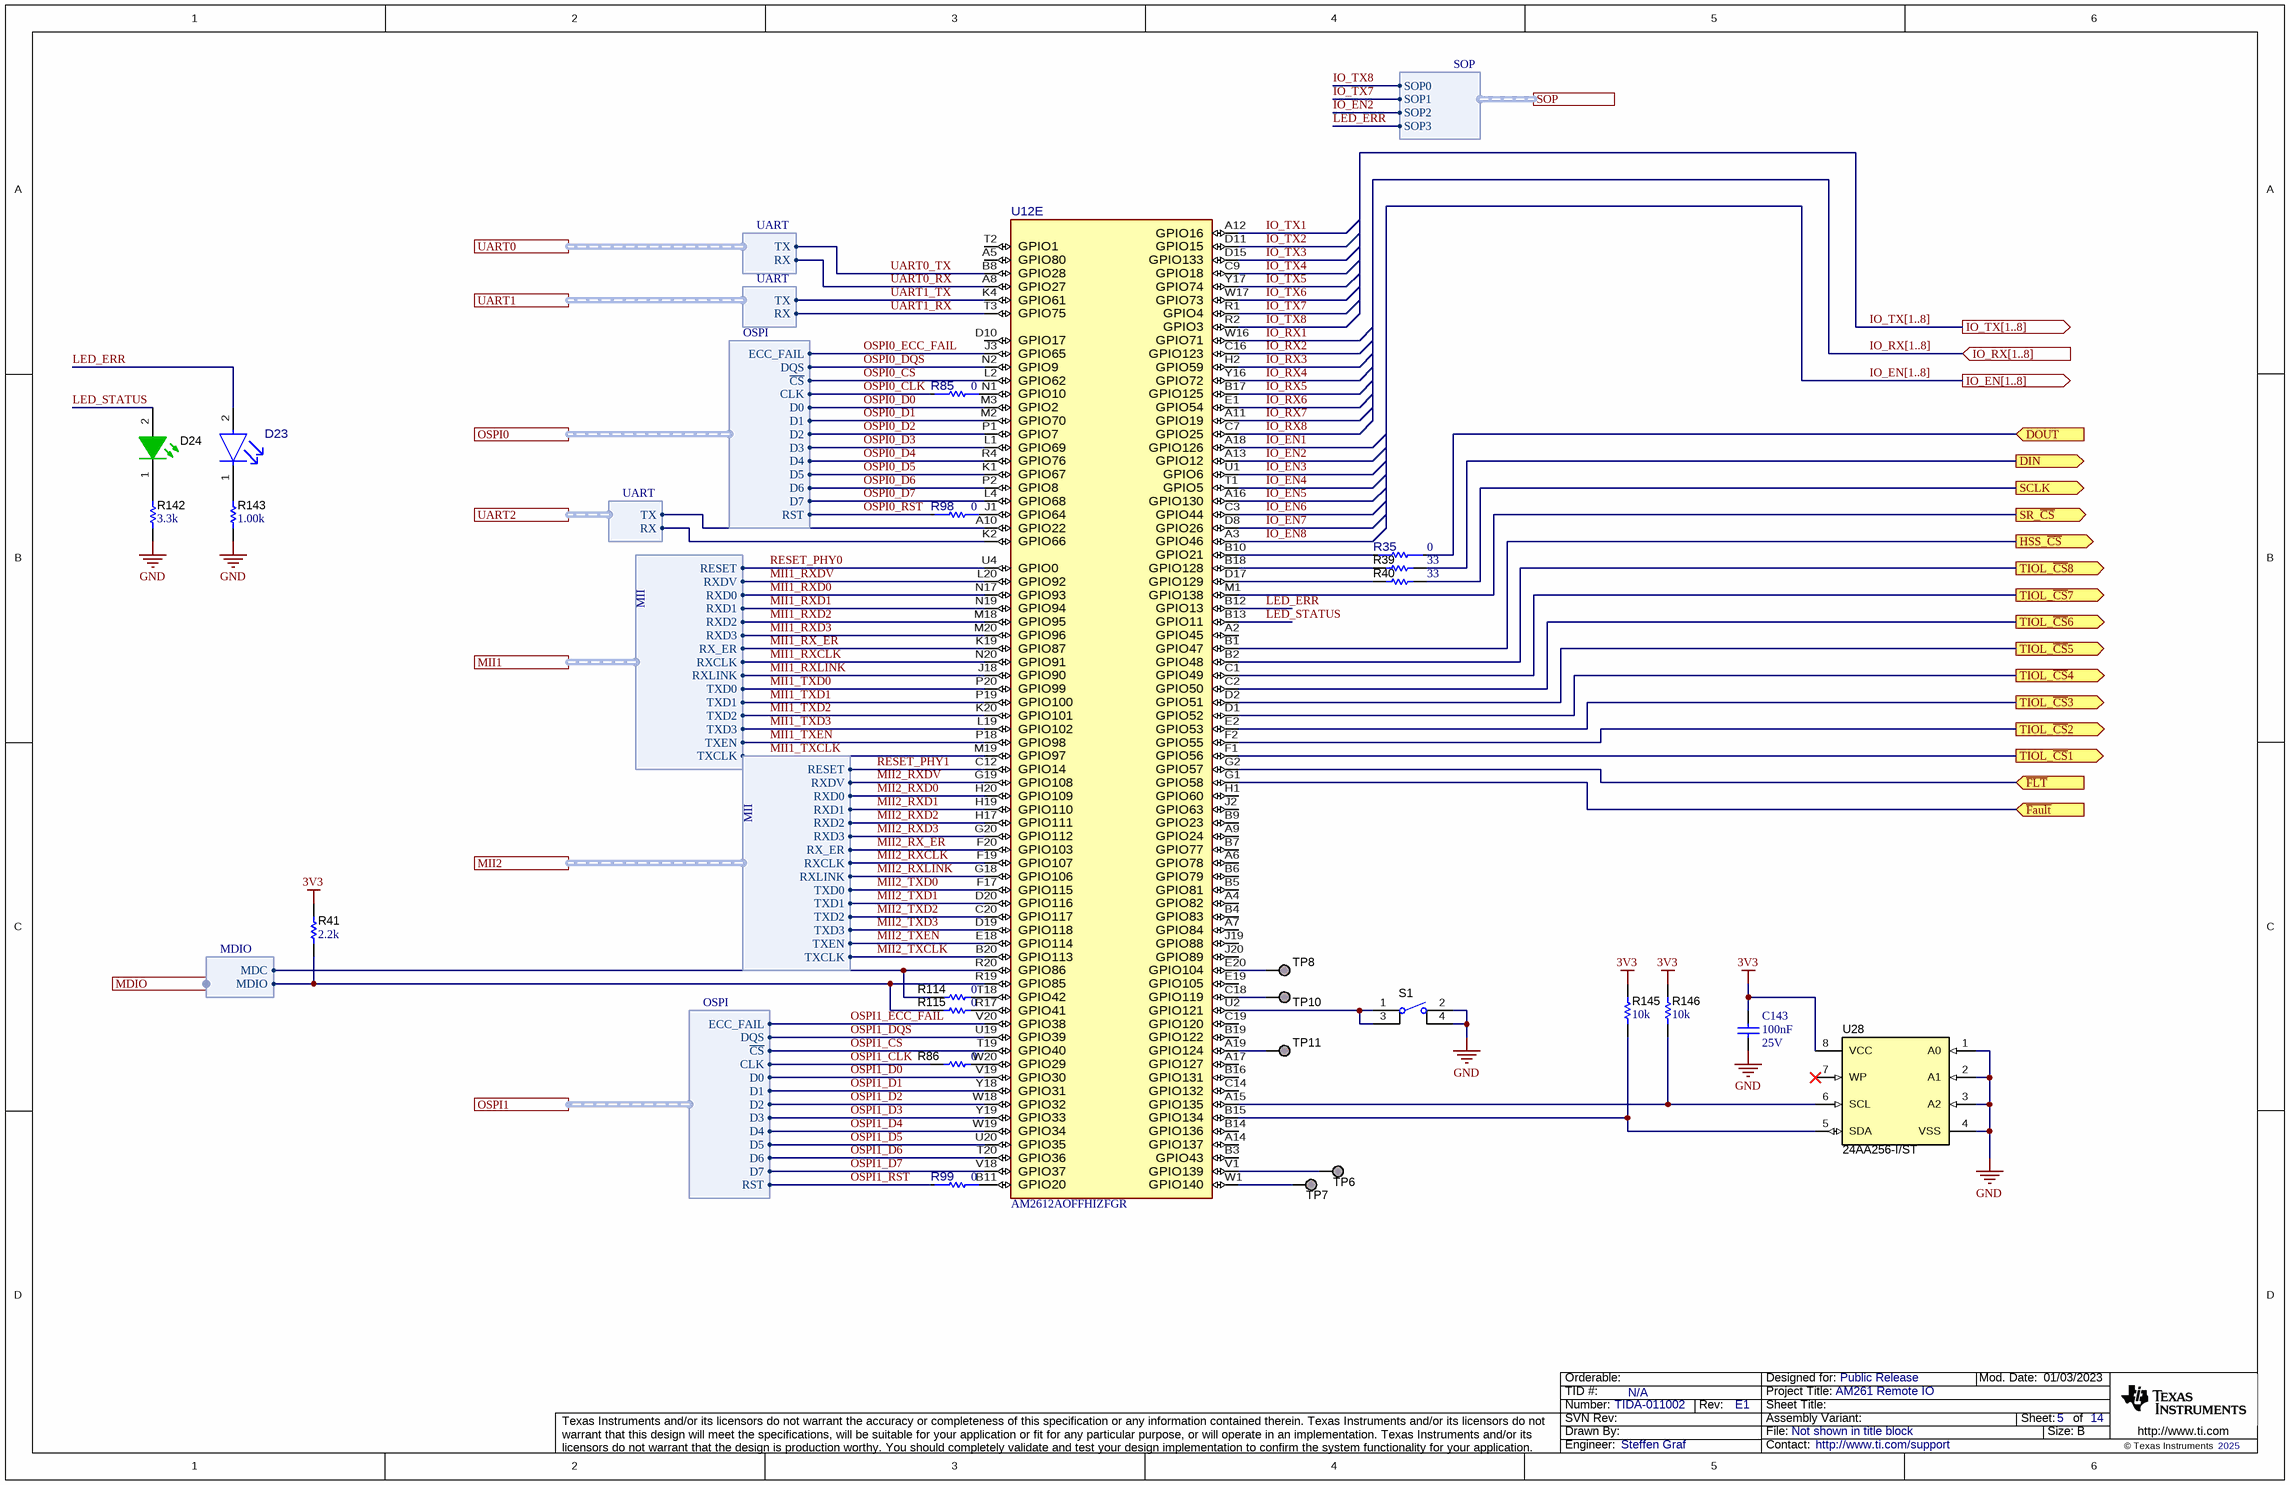
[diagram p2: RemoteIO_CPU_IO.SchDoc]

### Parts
C143  Cap_F: 100nF  Rated Voltage (DC): 25V  [WCAP-CSGP_0402_L1W0.5H0.5]  (hidden comment: 885012105018)
D23  150040RS73240  [FP-150040RS73220_0402-MFG]  (value not drawn)
D24  150040GS73240  [WL-SMCC_0402_Green]  (value not drawn)
R35  value 0  [FP-CRCW04020000Z0EDC_0402-MFG]  (hidden comment: CRCW04020000Z0EDC)
R39  ValueDisplayed: 33  [0402]  (hidden comment: CRCW040233R0JNED)
R40  ValueDisplayed: 33  [0402]  (hidden comment: CRCW040233R0JNED)
R41  ValueDisplayed: 2.2k  [0402]  (hidden comment: CRCW04022K20JNED)
R85  value 0  [FP-CRCW04020000Z0EDC_0402-MFG]  (hidden comment: CRCW04020000Z0EDC)
R86  ValueDisplayed: 0  [0201L]  (hidden comment: CRCW02010000Z0ED)
R98  value 0  [FP-CRCW04020000Z0EDC_0402-MFG]  (hidden comment: CRCW04020000Z0EDC)
R99  value 0  [FP-CRCW04020000Z0EDC_0402-MFG]  (hidden comment: CRCW04020000Z0EDC)
R114  ValueDisplayed: 0  [0201L]  (hidden comment: CRCW02010000Z0ED)
R115  ValueDisplayed: 0  [0201L]  (hidden comment: CRCW02010000Z0ED)
R142  ValueDisplayed: 3.3k  [0402]  (hidden comment: CRCW04023K30JNED)
R143  ValueDisplayed: 1.00k  [0402]  (hidden comment: CRCW04021K00FKED)
R145  ValueDisplayed: 10k  [0402]  (hidden comment: CRCW040210K0JNED)
R146  ValueDisplayed: 10k  [0402]  (hidden comment: CRCW040210K0JNED)
S1  434153017835  [SW_434153017835]  (value not drawn)
TP6  TESTPOINT  [TP_25MIL-SMT]  (value not drawn)  (no BOM)
TP7  TESTPOINT  [TP_25MIL-SMT]  (value not drawn)  (no BOM)
TP8  TESTPOINT  [TP_25MIL-SMT]  (value not drawn)  (no BOM)
TP10  TESTPOINT  [TP_25MIL-SMT]  (value not drawn)  (no BOM)
TP11  TESTPOINT  [TP_25MIL-SMT]  (value not drawn)  (no BOM)
U12  AM2612AOFFHIZFGR  [ZFG0304A-MFG]  (part E of 7)
U28  24AA256-I/ST  [TSSOP-8]

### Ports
DIN (out), DOUT (in), HSS_~{CS} (out), IO_EN[1..8] (out), IO_RX[1..8] (in), IO_TX[1..8] (out), MDIO (harness MDIO), MII1 (harness MII), MII2 (harness MII), OSPI0 (harness OSPI), OSPI1 (harness OSPI), SCLK (out), SOP (harness SOP), SR_~{CS} (out), TIOL_~{CS}1 (out), TIOL_~{CS}2 (out), TIOL_~{CS}3 (out), TIOL_~{CS}4 (out), TIOL_~{CS}5 (out), TIOL_~{CS}6 (out), TIOL_~{CS}7 (out), TIOL_~{CS}8 (out), UART0 (harness UART), UART1 (harness UART), UART2 (harness UART), ~{Fault} (in), ~{FLT} (in)

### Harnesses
MII: RXDV, RXD0, RXD1, RXD2, RXD3, RX_ER, RXCLK, RXLINK, TXD0, TXD1, TXD2, TXD3, TXEN, TXCLK, RESET
MDIO: MDC, MDIO
UART: TX, RX
OSPI: ~{CS}, CLK, D0, D1, D2, D3, D4, D5, D6, D7, DQS, ECC_FAIL, RST
SOP: SOP0, SOP1, SOP2, SOP3

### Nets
3V3: C143.2 R41.1 R145.1 R146.1 U28.8(VCC)
GND: C143.1 R142.1 R143.1 S1.2 S1.4 U28.1(A0) U28.2(A1) U28.3(A2) U28.4(VSS)
~{Fault}: U12.G1(GPIO58) ; port ~{Fault}
~{FLT}: U12.G2(GPIO57) ; port ~{FLT}
CS1: U12.F1(GPIO56) ; port TIOL_~{CS}1
CS2: U12.F2(GPIO55) ; port TIOL_~{CS}2
CS3: U12.E2(GPIO53) ; port TIOL_~{CS}3
CS4: U12.D1(GPIO52) ; port TIOL_~{CS}4
CS5: U12.D2(GPIO51) ; port TIOL_~{CS}5
CS6: U12.C2(GPIO50) ; port TIOL_~{CS}6
CS7: U12.C1(GPIO49) ; port TIOL_~{CS}7
CS8: U12.B2(GPIO48) ; port TIOL_~{CS}8
DIN: R39.2 ; port DIN
DOUT: R35.1 ; port DOUT
HSS_~{CS}: U12.B1(GPIO47) ; port HSS_~{CS}
IO_EN1: U12.A18(GPIO126)
IO_EN2: U12.A13(GPIO12) ; port SOP.SOP2
IO_EN3: U12.U1(GPIO6)
IO_EN4: U12.T1(GPIO5)
IO_EN5: U12.A16(GPIO130)
IO_EN6: U12.C3(GPIO44)
IO_EN7: U12.D8(GPIO26)
IO_EN8: U12.A3(GPIO46)
IO_RX1: U12.W16(GPIO71)
IO_RX2: U12.C16(GPIO123)
IO_RX3: U12.H2(GPIO59)
IO_RX4: U12.Y16(GPIO72)
IO_RX5: U12.B17(GPIO125)
IO_RX6: U12.E1(GPIO54)
IO_RX7: U12.A11(GPIO19)
IO_RX8: U12.C7(GPIO25)
IO_TX1: U12.A12(GPIO16)
IO_TX2: U12.D11(GPIO15)
IO_TX3: U12.D15(GPIO133)
IO_TX4: U12.C9(GPIO18)
IO_TX5: U12.Y17(GPIO74)
IO_TX6: U12.W17(GPIO73)
IO_TX7: U12.R1(GPIO4) ; port SOP.SOP1
IO_TX8: U12.R2(GPIO3) ; port SOP.SOP0
LED_ERR: D23.2(ANODE) U12.B12(GPIO13) ; port SOP.SOP3
LED_STATUS: D24.2(A) U12.B13(GPIO11)
MII1_RX_ER: U12.K19(GPIO87) ; port MII1.RX_ER
MII1_RXCLK: U12.N20(GPIO91) ; port MII1.RXCLK
MII1_RXD0: U12.N17(GPIO93) ; port MII1.RXD0
MII1_RXD1: U12.N19(GPIO94) ; port MII1.RXD1
MII1_RXD2: U12.M18(GPIO95) ; port MII1.RXD2
MII1_RXD3: U12.M20(GPIO96) ; port MII1.RXD3
MII1_RXDV: U12.L20(GPIO92) ; port MII1.RXDV
MII1_RXLINK: U12.J18(GPIO90) ; port MII1.RXLINK  [project net LED_Link]
MII1_TXCLK: U12.M19(GPIO97) ; port MII1.TXCLK
MII1_TXD0: U12.P20(GPIO99) ; port MII1.TXD0
MII1_TXD1: U12.P19(GPIO100) ; port MII1.TXD1
MII1_TXD2: U12.K20(GPIO101) ; port MII1.TXD2
MII1_TXD3: U12.L19(GPIO102) ; port MII1.TXD3
MII1_TXEN: U12.P18(GPIO98) ; port MII1.TXEN
MII2_RX_ER: U12.F20(GPIO103) ; port MII2.RX_ER
MII2_RXCLK: U12.F19(GPIO107) ; port MII2.RXCLK
MII2_RXD0: U12.H20(GPIO109) ; port MII2.RXD0
MII2_RXD1: U12.H19(GPIO110) ; port MII2.RXD1
MII2_RXD2: U12.H17(GPIO111) ; port MII2.RXD2
MII2_RXD3: U12.G20(GPIO112) ; port MII2.RXD3
MII2_RXDV: U12.G19(GPIO108) ; port MII2.RXDV
MII2_RXLINK: U12.G18(GPIO106) ; port MII2.RXLINK  [project net LED_Link]
MII2_TXCLK: U12.B20(GPIO113) ; port MII2.TXCLK
MII2_TXD0: U12.F17(GPIO115) ; port MII2.TXD0
MII2_TXD1: U12.D20(GPIO116) ; port MII2.TXD1
MII2_TXD2: U12.C20(GPIO117) ; port MII2.TXD2
MII2_TXD3: U12.D19(GPIO118) ; port MII2.TXD3
MII2_TXEN: U12.E18(GPIO114) ; port MII2.TXEN
OSPI0_~{CS}: U12.L2(GPIO62) ; port OSPI0.~{CS}
OSPI0_CLK: R85.1 ; port OSPI0.CLK
OSPI0_D0: U12.M3(GPIO2) ; port OSPI0.D0
OSPI0_D1: U12.M2(GPIO70) ; port OSPI0.D1
OSPI0_D2: U12.P1(GPIO7) ; port OSPI0.D2
OSPI0_D3: U12.L1(GPIO69) ; port OSPI0.D3
OSPI0_D4: U12.R4(GPIO76) ; port OSPI0.D4
OSPI0_D5: U12.K1(GPIO67) ; port OSPI0.D5
OSPI0_D6: U12.P2(GPIO8) ; port OSPI0.D6
OSPI0_D7: U12.L4(GPIO68) ; port OSPI0.D7
OSPI0_DQS: U12.N2(GPIO9) ; port OSPI0.DQS
OSPI0_ECC_FAIL: U12.J3(GPIO65) ; port OSPI0.ECC_FAIL
OSPI0_RST: R98.1 ; port OSPI0.RST
OSPI1_~{CS}: U12.T19(GPIO40) ; port OSPI1.~{CS}
OSPI1_CLK: R86.1 ; port OSPI1.CLK
OSPI1_D0: U12.V19(GPIO30) ; port OSPI1.D0
OSPI1_D1: U12.Y18(GPIO31) ; port OSPI1.D1
OSPI1_D2: U12.W18(GPIO32) ; port OSPI1.D2
OSPI1_D3: U12.Y19(GPIO33) ; port OSPI1.D3
OSPI1_D4: U12.W19(GPIO34) ; port OSPI1.D4
OSPI1_D5: U12.U20(GPIO35) ; port OSPI1.D5
OSPI1_D6: U12.T20(GPIO36) ; port OSPI1.D6
OSPI1_D7: U12.V18(GPIO37) ; port OSPI1.D7
OSPI1_DQS: U12.U19(GPIO39) ; port OSPI1.DQS
OSPI1_ECC_FAIL: U12.V20(GPIO38) ; port OSPI1.ECC_FAIL
OSPI1_RST: R99.1 ; port OSPI1.RST
RESET_PHY0: U12.U4(GPIO0) ; port MII1.RESET
RESET_PHY1: U12.C12(GPIO14) ; port MII2.RESET
SCLK: R40.2 ; port SCLK
SR_~{CS}: U12.M1(GPIO138) ; port SR_~{CS}
UART0_RX: U12.A8(GPIO27) ; port UART0.RX
UART0_TX: U12.B8(GPIO28) ; port UART0.TX
UART1_RX: U12.T3(GPIO75) ; port UART1.RX
UART1_TX: U12.K4(GPIO61) ; port UART1.TX
NetD23_1: D23.1(CATHODE) R143.2
NetD24_1: D24.1(K) R142.2
NetJ9_2: U12.K2(GPIO66) ; port UART2.RX
NetJ9_3: U12.A10(GPIO22) ; port UART2.TX
NetR35_2: R35.2 U12.B10(GPIO21)
NetR39_1: R39.1 U12.B18(GPIO128)
NetR40_1: R40.1 U12.D17(GPIO129)
NetR41_2: R41.2 R115.1 U12.R19(GPIO85) ; port MDIO.MDIO
NetR85_2: R85.2 U12.N1(GPIO10)
NetR86_2: R86.2 U12.W20(GPIO29)
NetR98_2: R98.2 U12.J1(GPIO64)
NetR99_2: R99.2 U12.B11(GPIO20)
NetR114_1: R114.1 U12.R20(GPIO86) ; port MDIO.MDC
NetR114_2: R114.2 U12.T18(GPIO42)
NetR115_2: R115.2 U12.R17(GPIO41)
NetR145_2: R145.2 U12.B15(GPIO134) U28.5(SDA)
NetR146_2: R146.2 U12.A15(GPIO135) U28.6(SCL)
NetS1_1: S1.1 S1.3 U12.U2(GPIO121)
NetTP6_1: TP6.1 U12.V1(GPIO139)
NetTP7_1: TP7.1 U12.W1(GPIO140)
NetTP8_1: TP8.1 U12.E20(GPIO104)
NetTP10_1: TP10.1 U12.C18(GPIO119)
NetTP11_1: TP11.1 U12.A19(GPIO124)

Not connected (* = marked no-connect by the designer): U12 A2(GPIO45) A4(GPIO82) A5(GPIO80) A6(GPIO78) A7(GPIO84) A9(GPIO24) A14(GPIO137) A17(GPIO127) B3(GPIO43) B4(GPIO83) B5(GPIO81) B6(GPIO79) B7(GPIO77) B9(GPIO23) B14(GPIO136) B16(GPIO131) B19(GPIO122) C14(GPIO132) C19(GPIO120) D10(GPIO17) E19(GPIO105) H1(GPIO60) J2(GPIO63) J19(GPIO88) J20(GPIO89) T2(GPIO1); U28 7(WP)*

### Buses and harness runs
bus IO_EN[1..8] = port IO_EN[1..8]
bus IO_RX[1..8] = port IO_RX[1..8]
bus IO_TX[1..8] = port IO_TX[1..8]

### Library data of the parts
C143 = CMP-0119143-1: as C135 on sheet RemoteIO_Ethernet
D23 = CMP-0122246-1: Red 624nm LED Indication - Discrete 2V 0402 (1005 Metric); Manufacturer: Wurth; Angle: 120°; LambdaP: 632nm; Power_TotalModule: 48mW; SizeZ_mm: 0.35mm; Tjmax_C: 115°C; Vr_V: 5V; AEC Qualified: No; Forward Current: 20mA; Led Orientation: Top View; Luminous Intensity: 110mcd
D24 = CMP-0081765-2: LED, Green, SMD; Manufacturer: Wurth Elektronik; Vr_V: 5V; Io_A: 20mA; Tjmax_C: 95°C; Ir_A: 10µA; Power_TotalModule: 99mW; Value2: 3.2V; SizeArea_mm2: 0.5; SizeX_mm: 1; Value1: 0.099W; Angle: 120; Type: InGaN; SizeAreaWB_mm2: 3
R35 R85 R98 R99 = CMP-0093210-1: Jumper 0.063W, 1/16W Chip Resistor 0402 (1005 Metric) - Thick Film; Manufacturer: Vishay; AEC Qualified: No; VDC_V: 50V; Power_W: 63mW; SizeZ_mm: 0.35mm
R39 R40 = CMP-0026908-3: RES, 33, 5%, 0.063 W, AEC-Q200 Grade 0, 0402; Manufacturer: Vishay-Dale; Power_W: 63mW; TempCo: 200 ppm/C; Value_Code: 33R0; Value: 33; EIA_Code: E24; SizeX_mm: 1; SizeY_mm: 0.5; SizeZ_mm: 0.6; Value2: 0.063W; AEC Qualified: Y; VDC_V: 50V; AEC Category: Q200; AEC Grade: 0
R41 = CMP-0026890-5: RES, 2.2 k, 5%, 0.063 W, AEC-Q200 Grade 0, 0402; Manufacturer: Vishay-Dale; Power_W: 63mW; TempCo: 200 ppm/C; Value_Code: 2k20; Value: 2.2k; EIA_Code: E24; SizeX_mm: 1; SizeY_mm: 0.5; SizeZ_mm: 0.6; Value2: 0.063W; AEC Qualified: Y; VDC_V: 50V; AEC Category: Q200; AEC Grade: 0
R86 R114 R115 = CMP-0027008-4: RES, 0, 5%, 0.05 W, 0201; Manufacturer: Vishay-Dale; Power_W: 50mW; TempCo: ppm/C; Value_Code: 0000; Value: 0; EIA_Code: E24; SizeX_mm: 0.6; SizeY_mm: 0.3; SizeZ_mm: 0.26; Value2: 0.05W; SizeArea_mm2: 0.18; AEC Qualified: N; AEC Category: Q200
R142 = CMP-0026918-5: RES, 3.3 k, 5%, 0.063 W, AEC-Q200 Grade 0, 0402; Manufacturer: Vishay-Dale; Power_W: 63mW; TempCo: 200 ppm/C; Value_Code: 3k30; Value: 3.3k; EIA_Code: E24; SizeX_mm: 1; SizeY_mm: 0.5; SizeZ_mm: 0.6; Value2: 0.063W; AEC Qualified: Y; VDC_V: 50V; AEC Category: Q200; AEC Grade: 0
R143 = CMP-0026071-3: RES, 1.00 k, 1%, 0.063 W, AEC-Q200 Grade 0, 0402; Manufacturer: Vishay-Dale; Power_W: 63mW; TempCo: 100 ppm/C; Value_Code: 1k00; Value: 1.00k; EIA_Code: E96; Res_ohm: 1k; SizeX_mm: 1; SizeY_mm: 0.5; SizeZ_mm: 0.6; Value2: 0.063W; AEC Qualified: Y; VDC_V: 50V; AEC Category: Q200; AEC Grade: 0
R145 R146 = CMP-0026825-5: as R164 on sheet RemoteIO_Ethernet
S1 = CMP-0002302-1: Switch, SPST, Off-Mom, 0.05 A, 12 VDC, SMD; Manufacturer: Wurth Elektronik; CurrentRating_mA: 50A; PositionCount: 1; SizeX_mm: 4.3; SizeY_mm: 2.9; SizeZ_mm: 1.9; SizeArea_mm2: 12.47; VDC_V: 12V; SizeAreaWB_mm2: 20.67
TP6-TP8 TP10 TP11 = CMP-0078143-4: TEST POINT.  No entry in BOM.
U12 = CMP-0126016-1: ARM® Cortex®-R5F Sitara™ Microcontroller IC 32-Bit Dual-Core 500MHz 512KB (512K x 8) Tightly Coupled Memory (TCM) 304-NFBGA (13.25x13.25); Manufacturer: Texas Instruments; SizeZ_mm: 1.3mm; AEC Qualified: No; Core Architecture: ARM Cortex-R5F; Data Bus Width: 32bits; Interface: I2C,SPI,UART,CAN,USB,LIN,Ethernet; Max Supply Voltage: 3.465V; Min Supply Voltage: 1.14V; Number Of A/D Converters: 3; Number Of Adc Channels: 7; Number Of Cores: 2; Number Of Ethernet Channels: 1; Number Of I/Os: 141; Number Of Pwm Channels: 10; Number Of Spi Channels: 4; Number Of Uart Channels: 6; Ram Size: 1.5MBytes; Standoff Height: 0.23mm; TJmax_C: +125°C
U28 = CMP-0005248-2: 256K I2C™ CMOS Serial EEPROM, TSSOP-8; Manufacturer: Microchip; SizeAreaWB_mm2: 42; SizeZ_mm: 1.2; SizeX_mm: 6.4; SizeY_mm: 3; SizeArea_mm2: 19.2

## Sheet RemoteIO_IO.SchDoc
size 431 x 279 mm; Date: Not shown in title block; ApprovedBy: Not shown in title block; CheckedBy: Not shown in title block; Author: Not shown in title block; CompanyName: Not shown in title block; Engineer: Not shown in title block; Organization: Not shown in title block; Address1: Not shown in title block; Address2: Not shown in title block; Address3: Not shown in title block; Address4: Not shown in title block; DocumentNumber: 12; Revision: Use project parameter SCH_Rev; SheetNumber: 12; SheetTotal: 14; PageSetup: Record=PageOptions¦CenterHorizontal=True¦CenterVertical=True¦PrintScale=1.00¦XCorrection=1.00¦YCorrection=1.00¦PrintKind=0¦BorderSize=5000000¦LeftOffset=0¦BottomOffset=0¦Orientation=2¦PaperLength=1000¦PaperWidth=1000¦Scale=100¦PaperSource=15¦PrintQuality=600¦MediaType=1¦DitherType=10¦PaperKind=Letter¦PrintScaleMode=1
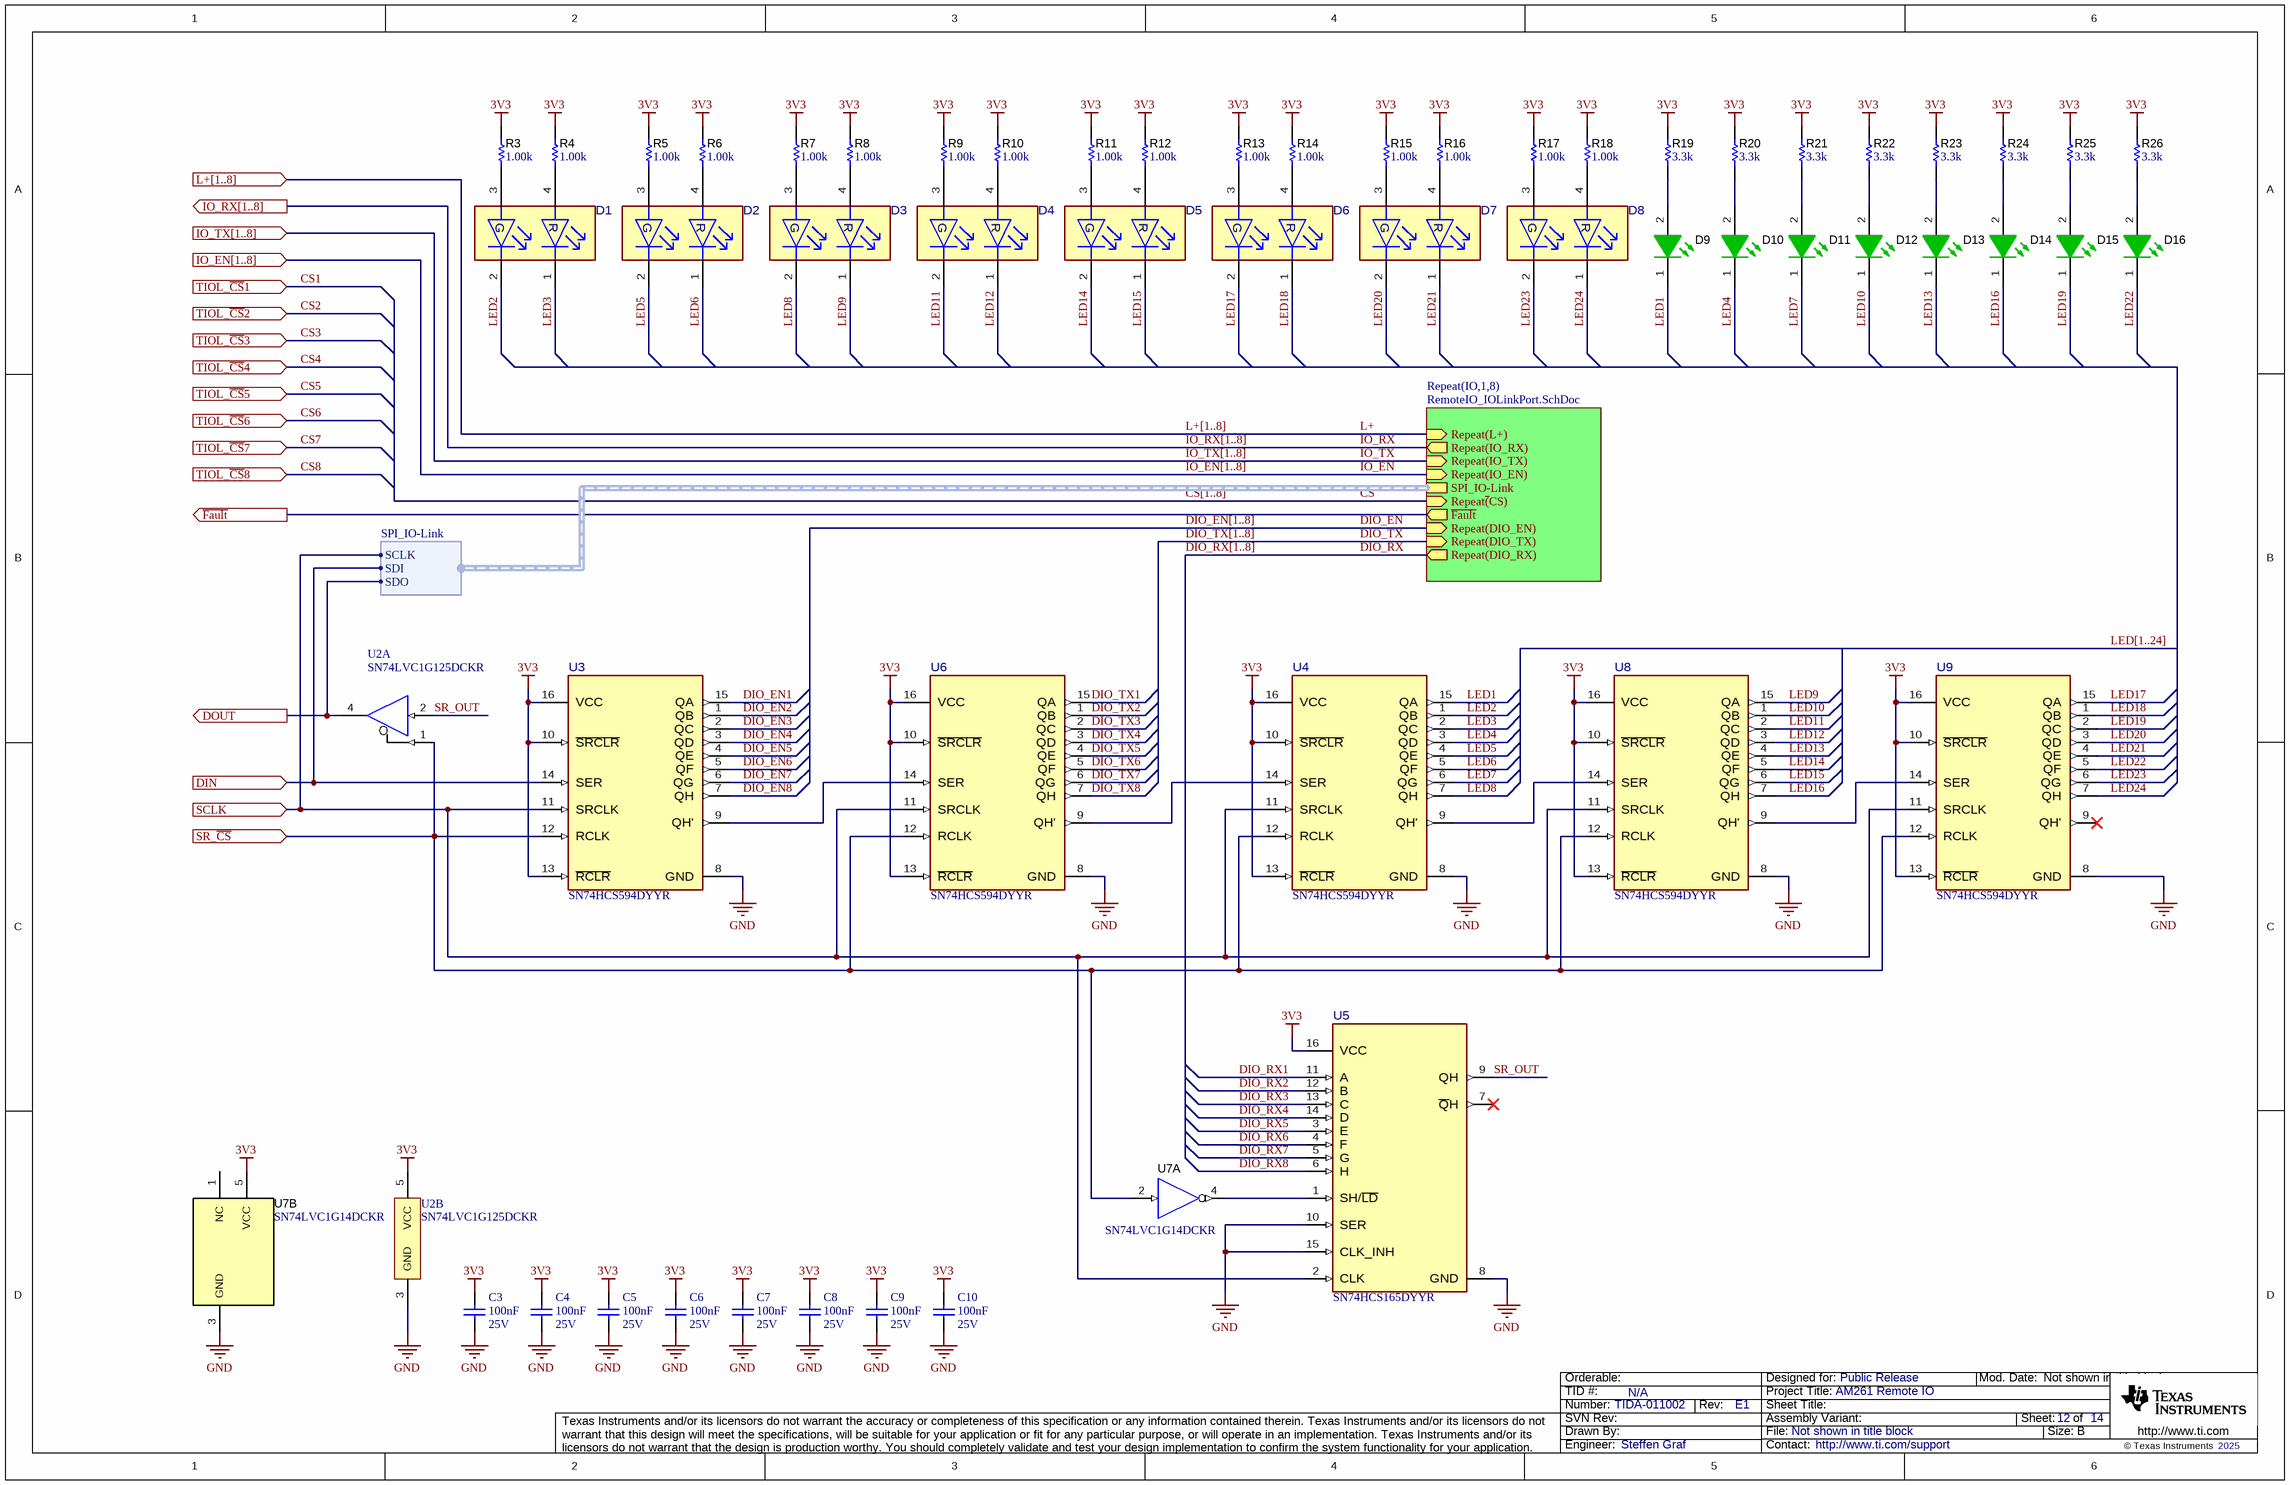
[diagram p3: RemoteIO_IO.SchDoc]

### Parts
C3  Cap_F: 100nF  Rated Voltage (DC): 25V  [WCAP-CSGP_0402_L1W0.5H0.5]  (hidden comment: 885012105018)
C4  Cap_F: 100nF  Rated Voltage (DC): 25V  [WCAP-CSGP_0402_L1W0.5H0.5]  (hidden comment: 885012105018)
C5  Cap_F: 100nF  Rated Voltage (DC): 25V  [WCAP-CSGP_0402_L1W0.5H0.5]  (hidden comment: 885012105018)
C6  Cap_F: 100nF  Rated Voltage (DC): 25V  [WCAP-CSGP_0402_L1W0.5H0.5]  (hidden comment: 885012105018)
C7  Cap_F: 100nF  Rated Voltage (DC): 25V  [WCAP-CSGP_0402_L1W0.5H0.5]  (hidden comment: 885012105018)
C8  Cap_F: 100nF  Rated Voltage (DC): 25V  [WCAP-CSGP_0402_L1W0.5H0.5]  (hidden comment: 885012105018)
C9  Cap_F: 100nF  Rated Voltage (DC): 25V  [WCAP-CSGP_0402_L1W0.5H0.5]  (hidden comment: 885012105018)
C10  Cap_F: 100nF  Rated Voltage (DC): 25V  [WCAP-CSGP_0402_L1W0.5H0.5]  (hidden comment: 885012105018)
D1  150066RG74000  [FP-150066RG74000_0606-MFG]  (value not drawn)
D2  150066RG74000  [FP-150066RG74000_0606-MFG]  (value not drawn)
D3  150066RG74000  [FP-150066RG74000_0606-MFG]  (value not drawn)
D4  150066RG74000  [FP-150066RG74000_0606-MFG]  (value not drawn)
D5  150066RG74000  [FP-150066RG74000_0606-MFG]  (value not drawn)
D6  150066RG74000  [FP-150066RG74000_0606-MFG]  (value not drawn)
D7  150066RG74000  [FP-150066RG74000_0606-MFG]  (value not drawn)
D8  150066RG74000  [FP-150066RG74000_0606-MFG]  (value not drawn)
D9  150040GS73240  [WL-SMCC_0402_Green]  (value not drawn)
D10  150040GS73240  [WL-SMCC_0402_Green]  (value not drawn)
D11  150040GS73240  [WL-SMCC_0402_Green]  (value not drawn)
D12  150040GS73240  [WL-SMCC_0402_Green]  (value not drawn)
D13  150040GS73240  [WL-SMCC_0402_Green]  (value not drawn)
D14  150040GS73240  [WL-SMCC_0402_Green]  (value not drawn)
D15  150040GS73240  [WL-SMCC_0402_Green]  (value not drawn)
D16  150040GS73240  [WL-SMCC_0402_Green]  (value not drawn)
R3  ValueDisplayed: 1.00k  [0402]  (hidden comment: CRCW04021K00FKED)
R4  ValueDisplayed: 1.00k  [0402]  (hidden comment: CRCW04021K00FKED)
R5  ValueDisplayed: 1.00k  [0402]  (hidden comment: CRCW04021K00FKED)
R6  ValueDisplayed: 1.00k  [0402]  (hidden comment: CRCW04021K00FKED)
R7  ValueDisplayed: 1.00k  [0402]  (hidden comment: CRCW04021K00FKED)
R8  ValueDisplayed: 1.00k  [0402]  (hidden comment: CRCW04021K00FKED)
R9  ValueDisplayed: 1.00k  [0402]  (hidden comment: CRCW04021K00FKED)
R10  ValueDisplayed: 1.00k  [0402]  (hidden comment: CRCW04021K00FKED)
R11  ValueDisplayed: 1.00k  [0402]  (hidden comment: CRCW04021K00FKED)
R12  ValueDisplayed: 1.00k  [0402]  (hidden comment: CRCW04021K00FKED)
R13  ValueDisplayed: 1.00k  [0402]  (hidden comment: CRCW04021K00FKED)
R14  ValueDisplayed: 1.00k  [0402]  (hidden comment: CRCW04021K00FKED)
R15  ValueDisplayed: 1.00k  [0402]  (hidden comment: CRCW04021K00FKED)
R16  ValueDisplayed: 1.00k  [0402]  (hidden comment: CRCW04021K00FKED)
R17  ValueDisplayed: 1.00k  [0402]  (hidden comment: CRCW04021K00FKED)
R18  ValueDisplayed: 1.00k  [0402]  (hidden comment: CRCW04021K00FKED)
R19  ValueDisplayed: 3.3k  [0402]  (hidden comment: CRCW04023K30JNED)
R20  ValueDisplayed: 3.3k  [0402]  (hidden comment: CRCW04023K30JNED)
R21  ValueDisplayed: 3.3k  [0402]  (hidden comment: CRCW04023K30JNED)
R22  ValueDisplayed: 3.3k  [0402]  (hidden comment: CRCW04023K30JNED)
R23  ValueDisplayed: 3.3k  [0402]  (hidden comment: CRCW04023K30JNED)
R24  ValueDisplayed: 3.3k  [0402]  (hidden comment: CRCW04023K30JNED)
R25  ValueDisplayed: 3.3k  [0402]  (hidden comment: CRCW04023K30JNED)
R26  ValueDisplayed: 3.3k  [0402]  (hidden comment: CRCW04023K30JNED)
U2  SN74LVC1G125DCKR  [DCK0005A_N]  (parts A,B of 2)
U3  SN74HCS594DYYR  [DYY0016A-MFG]
U4  SN74HCS594DYYR  [DYY0016A-MFG]
U5  SN74HCS165DYYR  [DYY0016A-MFG]
U6  SN74HCS594DYYR  [DYY0016A-MFG]
U7  SN74LVC1G14DCKR  [DCK0005A_N]  (parts A,B of 2)
U8  SN74HCS594DYYR  [DYY0016A-MFG]
U9  SN74HCS594DYYR  [DYY0016A-MFG]

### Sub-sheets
Repeat(IO,1,8) = RemoteIO_IOLinkPort.SchDoc: Repeat(L+) (in), SPI_IO-Link (harness SPI_IO-Link), Repeat(DIO_RX) (out), Repeat(DIO_EN) (in), Repeat(DIO_TX) (in), Repeat~{(}CS) (in), ~{Fault} (out), Repeat(IO_RX) (out), Repeat(IO_EN) (in), Repeat(IO_TX) (in)

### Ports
DIN (in), DOUT (out), IO_EN[1..8] (in), IO_RX[1..8] (out), IO_TX[1..8] (in), L+[1..8] (in), SCLK (in), SR_~{CS} (in), TIOL_~{CS}1 (in), TIOL_~{CS}2 (in), TIOL_~{CS}3 (in), TIOL_~{CS}4 (in), TIOL_~{CS}5 (in), TIOL_~{CS}6 (in), TIOL_~{CS}7 (in), TIOL_~{CS}8 (in), ~{Fault} (out)

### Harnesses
SPI_IO-Link: SCLK, SDI, SDO

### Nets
3V3: C3.2 C4.2 C5.2 C6.2 C7.2 C8.2 C9.2 C10.2 R3.2 R4.2 R5.2 R6.2 R7.2 R8.2 R9.2 R10.2 R11.2 R12.2 R13.2 R14.2 R15.2 R16.2 R17.2 R18.2 R19.2 R20.2 R21.2 R22.2 R23.2 R24.2 R25.2 R26.2 U2.5(VCC) U3.10(~{SRCLR}) U3.13(~{RCLR}) U3.16(VCC) U4.10(~{SRCLR}) U4.13(~{RCLR}) U4.16(VCC) U5.16(VCC) U6.10(~{SRCLR}) U6.13(~{RCLR}) U6.16(VCC) U7.5(VCC) U8.10(~{SRCLR}) U8.13(~{RCLR}) U8.16(VCC) U9.10(~{SRCLR}) U9.13(~{RCLR}) U9.16(VCC)
GND: C3.1 C4.1 C5.1 C6.1 C7.1 C8.1 C9.1 C10.1 U2.3(GND) U3.8(GND) U4.8(GND) U5.8(GND) U5.10(SER) U5.15(CLK_INH) U6.8(GND) U7.3(GND) U8.8(GND) U9.8(GND)
~{Fault}: port ~{Fault}, sheet Repeat(IO,1,8)/~{Fault}
DIN: U3.14(SER) ; port DIN, sheet Repeat(IO,1,8)/SPI_IO-Link.SDI
DIO_EN1: U3.15(QA)
DIO_EN2: U3.1(QB)
DIO_EN3: U3.2(QC)
DIO_EN4: U3.3(QD)
DIO_EN5: U3.4(QE)
DIO_EN6: U3.5(QF)
DIO_EN7: U3.6(QG)
DIO_EN8: U3.7(QH)
DIO_RX1: U5.11(A)
DIO_RX2: U5.12(B)
DIO_RX3: U5.13(C)
DIO_RX4: U5.14(D)
DIO_RX5: U5.3(E)
DIO_RX6: U5.4(F)
DIO_RX7: U5.5(G)
DIO_RX8: U5.6(H)
DIO_TX1: U6.15(QA)
DIO_TX2: U6.1(QB)
DIO_TX3: U6.2(QC)
DIO_TX4: U6.3(QD)
DIO_TX5: U6.4(QE)
DIO_TX6: U6.5(QF)
DIO_TX7: U6.6(QG)
DIO_TX8: U6.7(QH)
DOUT: U2.4(Y) ; port DOUT, sheet Repeat(IO,1,8)/SPI_IO-Link.SDO
LED1: D9.1(K) U4.15(QA)
LED2: D1.2(G_Cathode) U4.1(QB)
LED3: D1.1(R_Cathode) U4.2(QC)
LED4: D10.1(K) U4.3(QD)
LED5: D2.2(G_Cathode) U4.4(QE)
LED6: D2.1(R_Cathode) U4.5(QF)
LED7: D11.1(K) U4.6(QG)
LED8: D3.2(G_Cathode) U4.7(QH)
LED9: D3.1(R_Cathode) U8.15(QA)
LED10: D12.1(K) U8.1(QB)
LED11: D4.2(G_Cathode) U8.2(QC)
LED12: D4.1(R_Cathode) U8.3(QD)
LED13: D13.1(K) U8.4(QE)
LED14: D5.2(G_Cathode) U8.5(QF)
LED15: D5.1(R_Cathode) U8.6(QG)
LED16: D14.1(K) U8.7(QH)
LED17: D6.2(G_Cathode) U9.15(QA)
LED18: D6.1(R_Cathode) U9.1(QB)
LED19: D15.1(K) U9.2(QC)
LED20: D7.2(G_Cathode) U9.3(QD)
LED21: D7.1(R_Cathode) U9.4(QE)
LED22: D16.1(K) U9.5(QF)
LED23: D8.2(G_Cathode) U9.6(QG)
LED24: D8.1(R_Cathode) U9.7(QH)
SCLK: U3.11(SRCLK) U4.11(SRCLK) U5.2(CLK) U6.11(SRCLK) U8.11(SRCLK) U9.11(SRCLK) ; port SCLK, sheet Repeat(IO,1,8)/SPI_IO-Link.SCLK
SR_~{CS}: U2.1(~{OE}) U3.12(RCLK) U4.12(RCLK) U6.12(RCLK) U7.2(A) U8.12(RCLK) U9.12(RCLK) ; port SR_~{CS}
SR_OUT: U2.2(A) U5.9(QH)
NetD1_3: D1.3(G_Anode) R3.1
NetD1_4: D1.4(R_Anode) R4.1
NetD2_3: D2.3(G_Anode) R5.1
NetD2_4: D2.4(R_Anode) R6.1
NetD3_3: D3.3(G_Anode) R7.1
NetD3_4: D3.4(R_Anode) R8.1
NetD4_3: D4.3(G_Anode) R9.1
NetD4_4: D4.4(R_Anode) R10.1
NetD5_3: D5.3(G_Anode) R11.1
NetD5_4: D5.4(R_Anode) R12.1
NetD6_3: D6.3(G_Anode) R13.1
NetD6_4: D6.4(R_Anode) R14.1
NetD7_3: D7.3(G_Anode) R15.1
NetD7_4: D7.4(R_Anode) R16.1
NetD8_3: D8.3(G_Anode) R17.1
NetD8_4: D8.4(R_Anode) R18.1
NetD9_2: D9.2(A) R19.1
NetD10_2: D10.2(A) R20.1
NetD11_2: D11.2(A) R21.1
NetD12_2: D12.2(A) R22.1
NetD13_2: D13.2(A) R23.1
NetD14_2: D14.2(A) R24.1
NetD15_2: D15.2(A) R25.1
NetD16_2: D16.2(A) R26.1
NetU3_9: U3.9(QH') U6.14(SER)
NetU4_9: U4.9(QH') U8.14(SER)
NetU4_14: U4.14(SER) U6.9(QH')
NetU5_1: U5.1(SH/~{LD}) U7.4(Y)
NetU8_9: U8.9(QH') U9.14(SER)

Not connected (* = marked no-connect by the designer): U5 7(~{Q}H)*; U7 1(NC); U9 9(QH')*

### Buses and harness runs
bus CS[1..8]
bus DIO_EN[1..8]
bus DIO_RX[1..8]
bus DIO_TX[1..8]
bus IO_EN[1..8] = port IO_EN[1..8]
bus IO_RX[1..8] = port IO_RX[1..8]
bus IO_TX[1..8] = port IO_TX[1..8]
bus L+[1..8] = port L+[1..8]
bus LED[1..24]

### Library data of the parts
C3-C10 = CMP-0119143-1: as C135 on sheet RemoteIO_Ethernet
D1-D8 = CMP-0125609-1: Green, Red 520nm Green, 625nm Red LED Indication - Discrete 3.2V Green, 2V Red 0606 (1616 Metric); Manufacturer: Wurth; Angle: 130°; Color: Red, Green; LambdaD: 625/520nm; LambdaP: 630/515nm; SizeZ_mm: 0.8mm; Tjmax_C: 95°C; Vr_V: 5V; AEC Qualified: No; Forward Current: 20mA; Led Orientation: Top View; Luminous Intensity: 300/560mcd; Value: Red/Green
D9-D16 = CMP-0081765-2: as D24 on sheet RemoteIO_CPU_IO
R3-R18 = CMP-0026071-3: as R143 on sheet RemoteIO_CPU_IO
R19-R26 = CMP-0026918-5: as R142 on sheet RemoteIO_CPU_IO
U2 = CMP-0051326-3: Single Bus Buffer Gate With 3-State Outputs, DCK0005A, LARGE T&R; Manufacturer: Texas Instruments; Bits(#): 1; tpd @ Nom Voltage(Max)(ns): 9,5.5,4.5,4; 3-State Output: Yes; Output Type: CMOS; Sub-Family: Non-Inverting Buffer/Driver; Logic: True; Output Drive (IOL/IOH)(Max)(mA): 32/-32; Voltage(Nom)(V): 1.8,2.5,3.3,5; ICC @ Nom Voltage(Max)(mA): 0.01; Technology Family: LVC; VCC(Min)(V): 1.65; VCC(Max)(V): 5.5; F @ Nom Voltage(Max)(Mhz): 150; Rating: Catalog; Input Type: CMOS/TTL; Schmitt Trigger: No; AEC Category: Q200; AEC Qualified: N; CompType: IC; SizeAreaWB_mm2: 9.3; SizeArea_mm2: 4.2; SizeX_mm: 2.1; SizeY_mm: 2.0; SizeZ_mm: 1.1
U3 U4 U6 U8 U9 = CMP-0093041-1: Eight-bit shift registers with Schmitt-trigger inputs and with output registers; Manufacturer: Texas Instruments; Number Of Inputs: 5; Max Supply Voltage: 6V; Min Supply Voltage: 2V; Propagation Delay: 19ns; Frequency_Fixed: 115MHz; AEC Qualified: No; Standoff Height: 0mm; TJmax_C: +150°C; TaMin_C: -40°C; PositionCount: 1; Nominal Supply Current: 0.1uA; SizeZ_mm: 1.1mm; TaMax_C: +125°C; Number Of Outputs: 8
U5 = CMP-0093040-1: Counter Shift Registers 8-bit parallel-load shift registers with Schmitt-trigger inputs; Manufacturer: Texas Instruments; TaMin_C: -40°C; SizeZ_mm: 1.1mm; PositionCount: 1; TaMax_C: +125°C; Number Of Inputs: 8; Frequency_Fixed: 170MHz; Propagation Delay: 39ns; Max Supply Voltage: 6V; Min Supply Voltage: 2V; AEC Qualified: No; TJmax_C: +150°C; Standoff Height: 0mm; Nominal Supply Current: 0.1uA
U7 = CMP-0051641-4: Single Schmitt-Trigger Inverter, DCK0005A (SOT-SC70-5); Manufacturer: Texas Instruments; Alternate PartNumber: SN74LVC1G14DCKT; Output Drive (IOL/IOH)(Max)(mA): 32/-32; Schmitt Trigger: Yes; Logic: Inverting; Bits(#): 1; Rating: Catalog; tpd @ Nom Voltage(Max)(ns): 11,6.5,5.5,5; Voltage(Nom)(V): 1.8,2.5,3.3,5; Output Type: CMOS; VCC(Min)(V): 1.65; ICC @ Nom Voltage(Max)(mA): 0.01; Input Type: CMOS/TTL; F @ Nom Voltage(Max)(Mhz): 150; VCC(Max)(V): 5.5; 3-State Output: No; AEC Category: Q200; AEC Qualified: N; CompType: IC; Green_Lifecycle: Active; Green_REACh: Passed; SizeAreaWB_mm2: 9.3; SizeArea_mm2: 4.2; SizeX_mm: 2.1; SizeY_mm: 2.0; SizeZ_mm: 1.1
